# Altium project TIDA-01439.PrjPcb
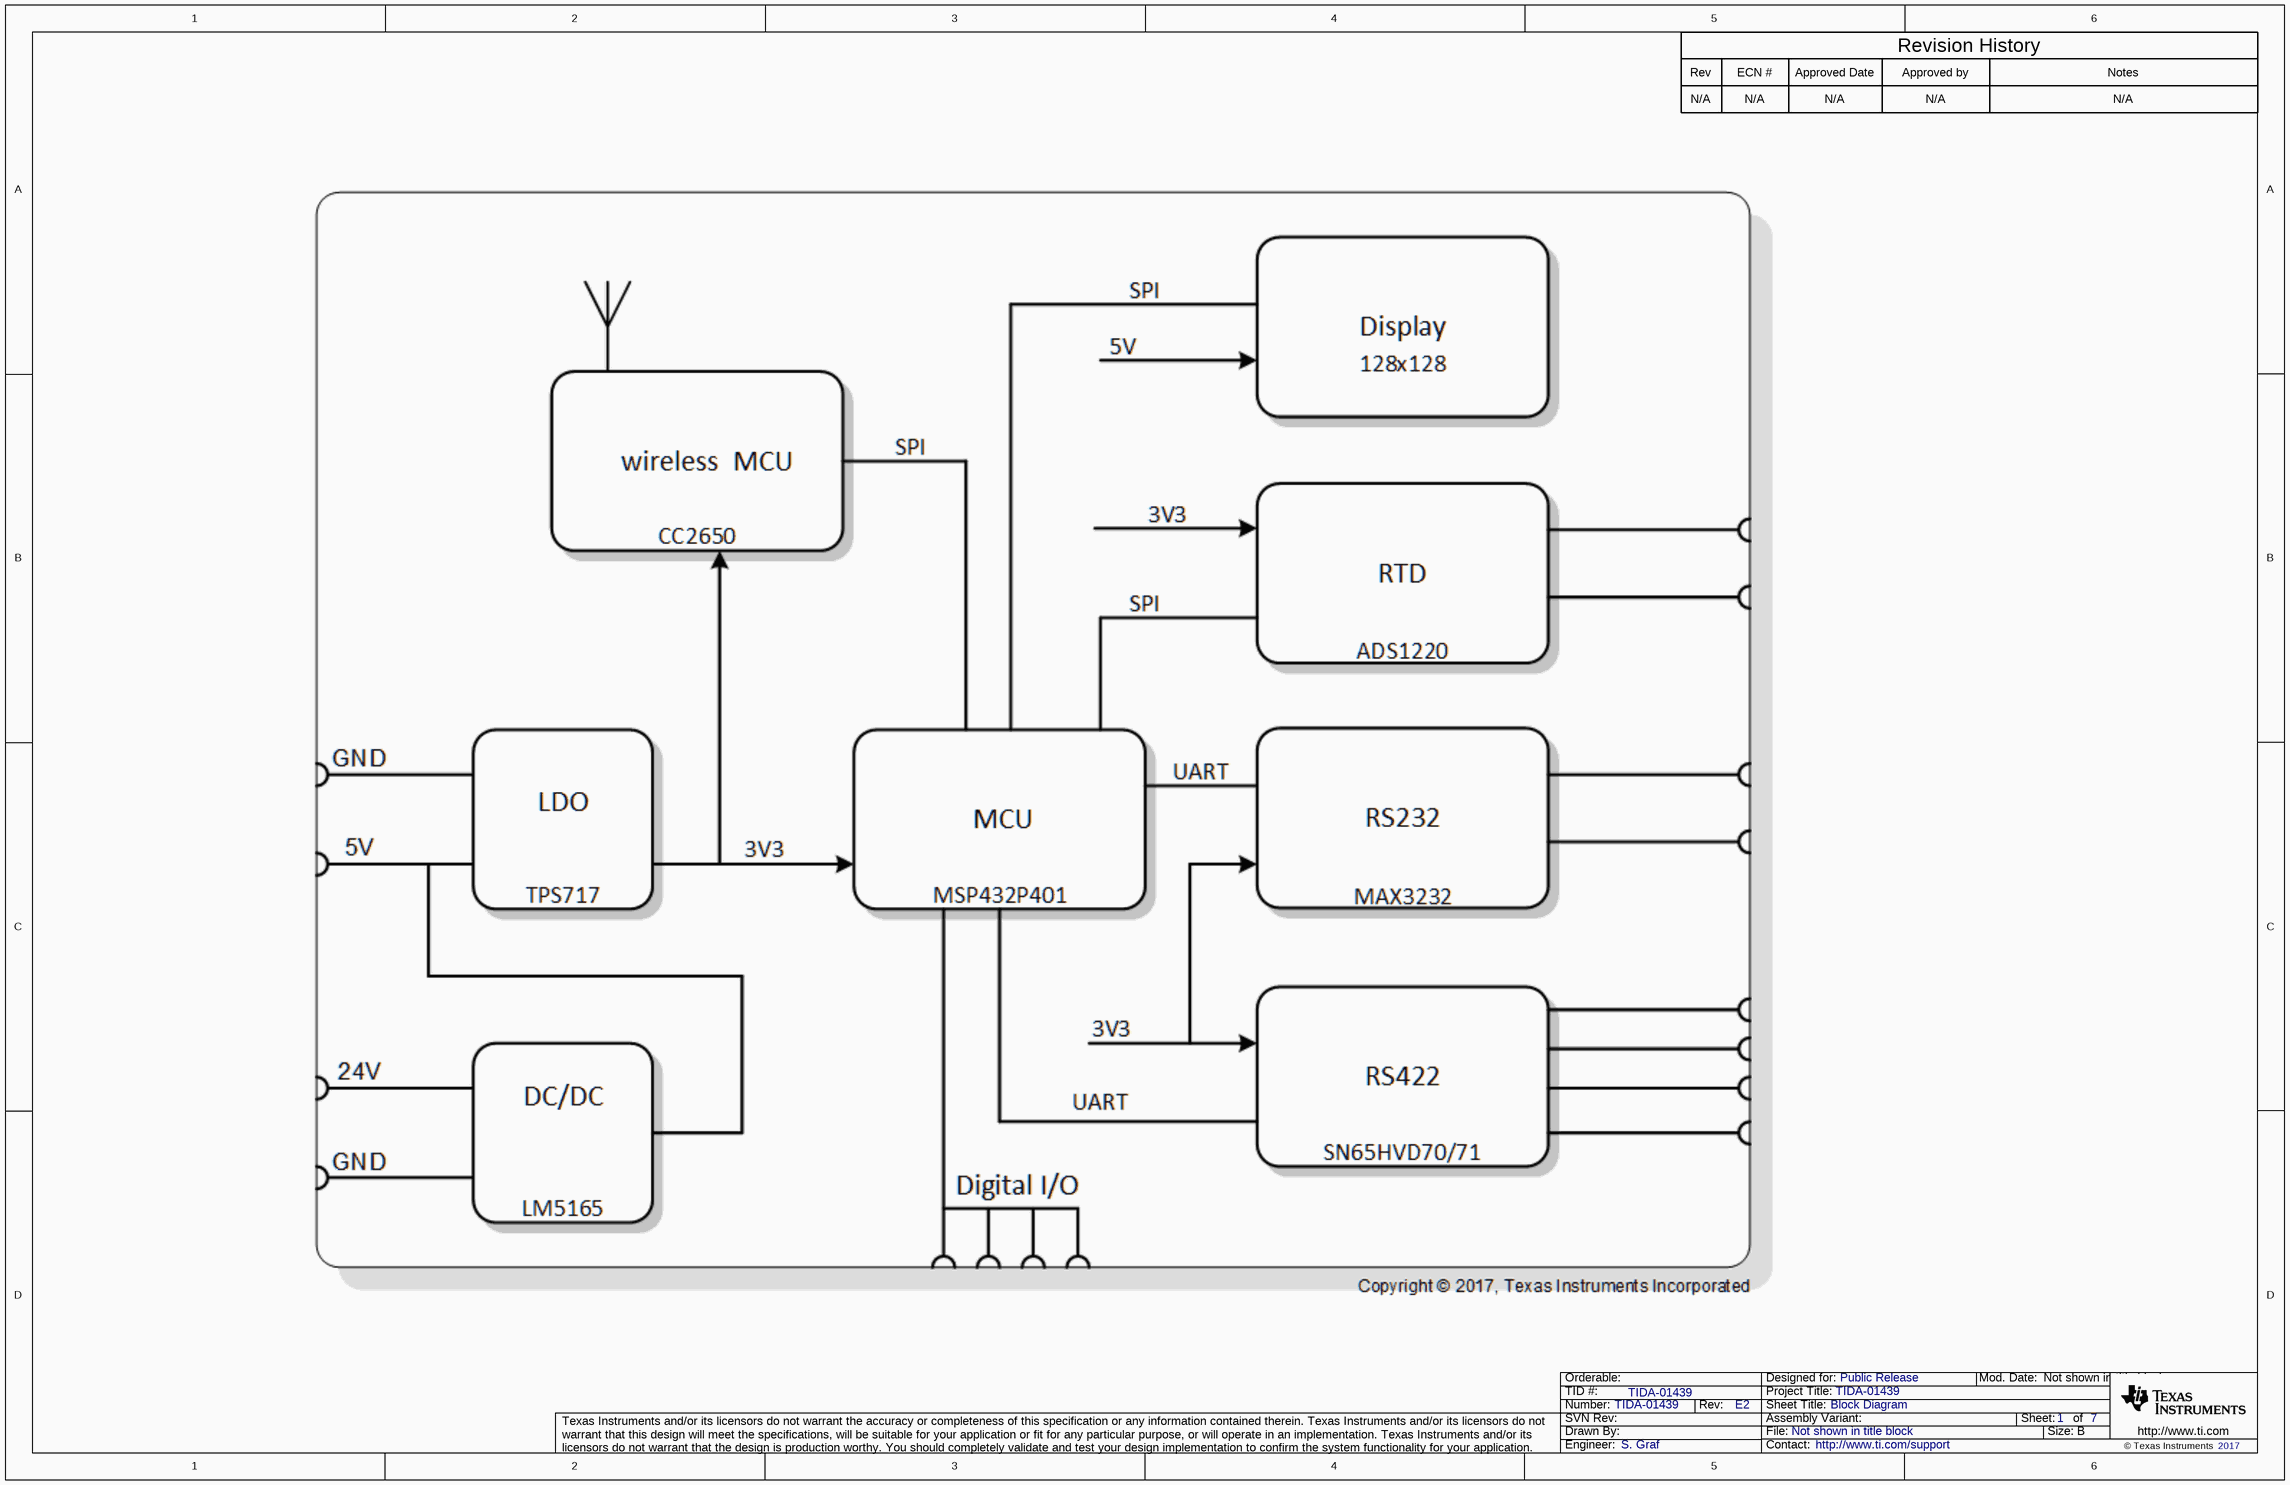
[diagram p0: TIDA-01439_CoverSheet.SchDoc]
CopyrightYear: 2017; PCB_Layout: K. Hacker (GCD); PCB_Rev: E2; PRJ_Customer: Public Release; PRJ_Engineer: S. Graf; PRJ_Number: TIDA-01439; PRJ_Title: TIDA-01439; SCH_Rev: E2; TechSupport: http://www.ti.com/support; TID: TIDA-01439
7 sheets, 144 parts. Net scope: global (net labels, ports and power ports of the same name join across sheets).
Board file: TIDA-01439_PCB.PcbDoc
Sheets:
  TIDA-01439_CoverSheet.SchDoc
  TIDA-01439_CC2650.SchDoc
  TIDA-01439_MSP432.SchDoc
  TIDA-01439_RTD.SchDoc
  TIDA-01439_Interface.SchDoc
  TIDA-01439_Powersupply.SchDoc
  TIDA-01439_EVM_Hardware.SchDoc

## Sheet TIDA-01439_CoverSheet.SchDoc: Block Diagram
size 431 x 279 mm; Date: Not shown in title block; ApprovedBy: Not shown in title block; CheckedBy: Not shown in title block; Author: Not shown in title block; CompanyName: Not shown in title block; Engineer: Not shown in title block; Organization: Not shown in title block; Address1: Not shown in title block; Address2: Not shown in title block; Address3: Not shown in title block; Address4: Not shown in title block; DocumentNumber: 1; Revision: Use project parameter SCH_Rev; SheetNumber: 1; SheetTotal: 7; PageSetup: Record=PageOptions¦CenterHorizontal=True¦CenterVertical=True¦PrintScale=1.00¦XCorrection=1.00¦YCorrection=1.00¦PrintKind=0¦BorderSize=5000000¦LeftOffset=0¦BottomOffset=0¦Orientation=2¦PaperLength=1000¦PaperWidth=1000¦Scale=100¦PaperSource=15¦PrintQuality=600¦MediaType=1¦DitherType=10¦PaperKind=Letter¦PrintScaleMode=1

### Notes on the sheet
- Rev
- N/A
- ECN #
- Approved Date
- Approved by
- Revision History
- Notes

## Sheet TIDA-01439_CC2650.SchDoc
size 431 x 279 mm; Date: Not shown in title block; ApprovedBy: Not shown in title block; CheckedBy: Not shown in title block; Author: Not shown in title block; CompanyName: Not shown in title block; Engineer: Not shown in title block; Organization: Not shown in title block; Address1: Not shown in title block; Address2: Not shown in title block; Address3: Not shown in title block; Address4: Not shown in title block; DocumentNumber: 1; Revision: Use project parameter SCH_Rev; SheetNumber: 2; SheetTotal: 7; PageSetup: Record=PageOptions¦CenterHorizontal=True¦CenterVertical=True¦PrintScale=1.00¦XCorrection=1.00¦YCorrection=1.00¦PrintKind=0¦BorderSize=5000000¦LeftOffset=0¦BottomOffset=0¦Orientation=2¦PaperLength=1000¦PaperWidth=1000¦Scale=100¦PaperSource=15¦PrintQuality=600¦MediaType=1¦DitherType=10¦PaperKind=Letter¦PrintScaleMode=1
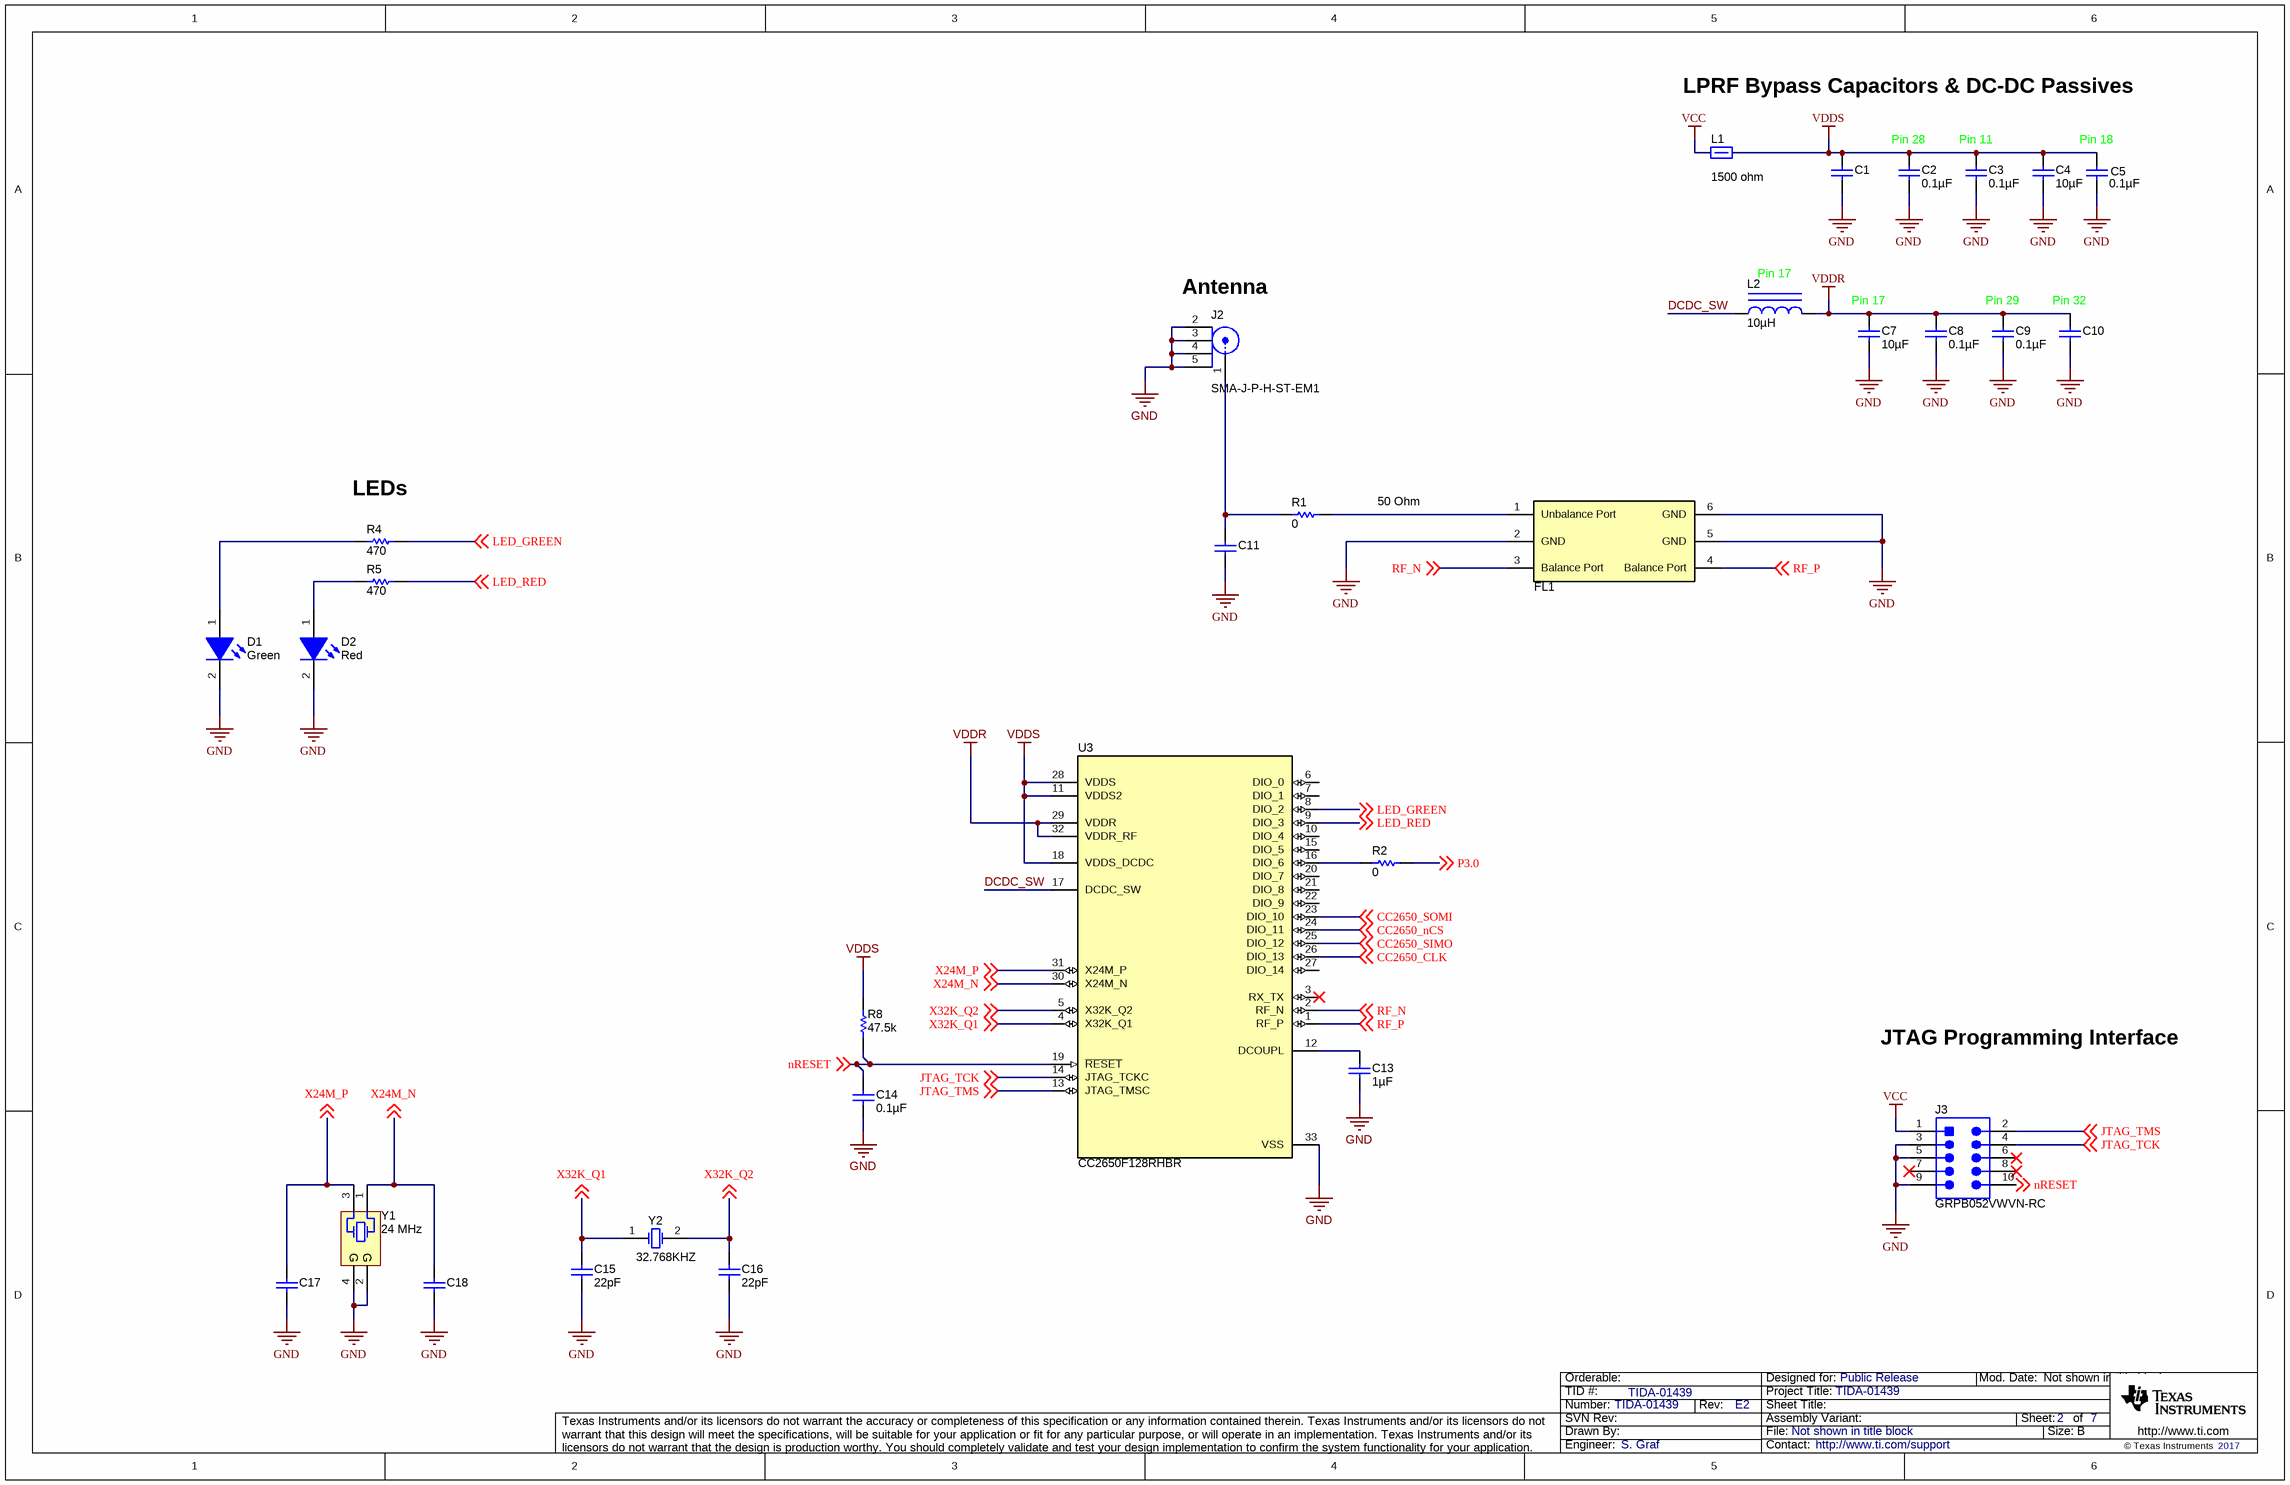
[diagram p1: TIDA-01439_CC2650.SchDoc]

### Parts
C1  Used in BOM report  [0603]  (value not drawn)
C2  ValueDisplayed: 0.1µF  [0402]  (hidden comment: GRM155R70J104KA01D)
C3  ValueDisplayed: 0.1µF  [0402]  (hidden comment: GRM155R70J104KA01D)
C4  ValueDisplayed: 10µF  [0805_HV]  (hidden comment: GRM21BR70J106KE76L)
C5  ValueDisplayed: 0.1µF  [0402]  (hidden comment: GRM155R70J104KA01D)
C7  ValueDisplayed: 10µF  [0805_HV]  (hidden comment: GRM21BR70J106KE76L)
C8  ValueDisplayed: 0.1µF  [0402]  (hidden comment: GRM155R70J104KA01D)
C9  ValueDisplayed: 0.1µF  [0402]  (hidden comment: GRM155R70J104KA01D)
C10  Used in BOM report  [0402]  (value not drawn)
C11  Used in BOM report  [0402]  (value not drawn)
C13  ValueDisplayed: 1µF  [0603]  (hidden comment: GRM188R70J105KA01D)
C14  ValueDisplayed: 0.1µF  [0402]  (hidden comment: GRM155R70J104KA01D)
C15  ValueDisplayed: 22pF  [0603]  (hidden comment: 06035A220JAT2A)
C16  ValueDisplayed: 22pF  [0603]  (hidden comment: 06035A220JAT2A)
C17  Used in BOM report  [0603]  (value not drawn)
C18  Used in BOM report  [0603]  (value not drawn)
D1  value Green  [KPTL-3216-01_Green]  (hidden comment: KPTL-3216CGCK-01)
D2  value Red  [KPTL-3216-01_Red]  (hidden comment: KPTL-3216SURCK-01)
FL1  LFB182G45BG5D920  [Murata_LFB182G45BG5D920]  (value not drawn)
J2  SMA-J-P-H-ST-EM1  [Samtec_SMA-J-P-H-ST-EM1]
J3  GRPB052VWVN-RC  [CONN_GRPB052VWVN-RC]
L1  value 1500 ohm  [0603]  (hidden comment: BLM18HE152SN1D)
L2  ValueDisplayed: 10µH  [0805_HV]  (hidden comment: CKS2125100M-T)
R1  ValueDisplayed: 0  [0402]  (hidden comment: CRCW04020000Z0ED)
R2  ValueDisplayed: 0  [0402]  (hidden comment: CRCW04020000Z0ED)
R4  ValueDisplayed: 470  [0402]  (hidden comment: CRCW0402470RJNED)
R5  ValueDisplayed: 470  [0402]  (hidden comment: CRCW0402470RJNED)
R8  ValueDisplayed: 47.5k  [0402]  (hidden comment: CRCW040247K5FKED)
U3  CC2650F128RHBR  [RHB0032E]
Y1  Frequency: 24 MHz  [EPSON_TSX-3225]  (hidden comment: TSX-3225 24.0000MF20G-AC3)
Y2  Frequency: 32.768KHZ  [Epson_FC-12M]  (hidden comment: FC-12M 32.7680KA-A3)

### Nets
GND: C1.2 C2.2 C3.2 C4.2 C5.2 C7.2 C8.2 C9.2 C10.2 C11.2 C13.2 C14.2 C15.1 C16.2 C17.2 C18.2 D1.2(K) D2.2(K) FL1.2(GND) FL1.5(GND) FL1.6(GND) J2.2 J2.3 J2.4 J2.5 J3.3 J3.5 J3.9 U3.33(VSS) Y1.2(GND) Y1.4(GND)
VCC: J3.1 L1.2
VDDR: C7.1 C8.1 C9.1 C10.1 L2.2 U3.29(VDDR) U3.32(VDDR_RF)
VDDS: C1.1 C2.1 C3.1 C4.1 C5.1 L1.1 R8.2 U3.11(VDDS2) U3.18(VDDS_DCDC) U3.28(VDDS)
CC2650_CLK: U3.26(DIO_13) ; off-sheet CC2650_CLK
CC2650_nCS: U3.24(DIO_11) ; off-sheet CC2650_nCS
CC2650_SIMO: U3.25(DIO_12) ; off-sheet CC2650_SIMO
CC2650_SOMI: U3.23(DIO_10) ; off-sheet CC2650_SOMI
DCDC_SW: L2.1 U3.17(DCDC_SW)
JTAG_TCK: J3.4 U3.14(JTAG_TCKC) ; off-sheet JTAG_TCK
JTAG_TMS: J3.2 U3.13(JTAG_TMSC) ; off-sheet JTAG_TMS
LED_GREEN: R4.2 U3.8(DIO_2) ; off-sheet LED_GREEN
LED_RED: R5.1 U3.9(DIO_3) ; off-sheet LED_RED
nRESET: C14.1 J3.10 R8.1 U3.19(~{RESET}) ; off-sheet nRESET
P3.0: R2.2 ; off-sheet P3.0
RF_N: FL1.3(Balance_Port) U3.2(RF_N) ; off-sheet RF_N
RF_P: FL1.4(Balance_Port) U3.1(RF_P) ; off-sheet RF_P
X24M_N: C18.1 U3.30(X24M_N) Y1.1 ; off-sheet X24M_N
X24M_P: C17.1 U3.31(X24M_P) Y1.3 ; off-sheet X24M_P
X32K_Q1: C15.2 U3.4(X32K_Q1) Y2.1(OSC1) ; off-sheet X32K_Q1
X32K_Q2: C16.1 U3.5(X32K_Q2) Y2.2(OSC2) ; off-sheet X32K_Q2
NetC11_1: C11.1 J2.1 R1.1
NetC13_1: C13.1 U3.12(DCOUPL)
NetD1_1: D1.1(A) R4.1
NetD2_1: D2.1(A) R5.2
NetFL1_1: FL1.1(Unbalance_Port) R1.2
NetR2_1: R2.1 U3.16(DIO_6)

Not connected (* = marked no-connect by the designer): J3 6* 7* 8*; U3 3(RX_TX)* 6(DIO_0) 7(DIO_1) 10(DIO_4) 15(DIO_5) 20(DIO_7) 21(DIO_8) 22(DIO_9) 27(DIO_14)

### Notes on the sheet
- LPRF Bypass Capacitors & DC-DC Passives
- (near C2) Pin 28
- (near C3) Pin 11
- (near C5) Pin 18
- (near J2) Antenna
- (near L2) Pin 17
- (near C7) Pin 17
- (near C9) Pin 29
- (near C10) Pin 32
- (near R4) LEDs
- 50 Ohm
- JTAG Programming Interface

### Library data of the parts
C1 C10 C11 C17 C18 = Capacitor: CAP, CERM, xxxF, xxV, [TempCo], xx%, [PackageReference]; Polarized: N; U/M: EA
C2 C3 C5 C8 C9 C14 = GRM155R70J104KA01D: CAP, CERM, 0.1 µF, 6.3 V, +/- 10%, X7R, 0402; Manufacturer: MuRata; Polarized: N; CompType: Capacitor; Value: 0.1uF; U/M: EA; Cap_F: 0.0000001; Tolerance_%: 10; Value1: Unknown; VDC_V: 6.3; Value2: 6.3V; TaMin_C: -55; TaMax_C: 125; AEC Category: Q200
C4 C7 = GRM21BR70J106KE76L: CAP, CERM, 10 µF, 6.3 V, +/- 10%, X7R, 0805; Manufacturer: MuRata; Polarized: N; CompType: Capacitor; Value: 10uF; U/M: EA; Cap_F: 0.00001; Tolerance_%: 10; Value1: Unknown; VDC_V: 6.3; Value2: 6.3V; TaMin_C: -55; TaMax_C: 125; Cap_Case: 0805; AEC Category: Q200
C13 = GRM188R70J105KA01D: CAP, CERM, 1 µF, 6.3 V, +/- 10%, X7R, 0603; Manufacturer: MuRata; Polarized: N; CompType: Capacitor; Value: 1uF; U/M: EA; Cap_F: 0.000001; Tolerance_%: 10; Value1: Unknown; VDC_V: 6.3; Value2: 6.3V; TaMin_C: -55; TaMax_C: 125; AEC Category: Q200
C15 C16 = 06035A220JAT2A: CAP, CERM, 22 pF, 50 V,+/- 5%, C0G/NP0, 0603; Manufacturer: AVX; Polarized: N; CompType: Capacitor; Value: 22pF; U/M: EA; Cap_F: 0.000000000022; Tolerance_%: 5; ESR_ohm: 0.259; Value1: 0.259 ohm; VDC_V: 50; Value2: 50V; TaMin_C: -55; TaMax_C: 125; SizeArea_mm2: 1.28; SizeAreaWB_mm2: 4.68; SizeX_mm: 1.6; SizeY_mm: 0.8; SizeZ_mm: 1; AEC Category: Q200; Green_Lifecycle: Active; Green_REACh: Passed
D1 = KPTL-3216CGCK-01: LED, Green, SMD; Manufacturer: Kingbright; Type: AlInGaP; Vf_V: 2.1; Value2: 2.1V; Io_A: 0.02; Vr_V: 5; Ir_A: 1e-005; Tjmax_C: 85; Power_TotalModule: 0.075; Value1: 0.075W; Angle: 70; U/M: EA; SizeAreaWB_mm2: 10.92; SizeArea_mm2: 5.12; SizeX_mm: 3.2; SizeY_mm: 1.6; SizeZ_mm: 0.35
D2 = KPTL-3216SURCK-01: LED, Red, SMD; Manufacturer: Kingbright; Type: AlInGaP; Vf_V: 1.95; Value2: 1.95V; Io_A: 0.02; Vr_V: 5; Ir_A: 1e-005; Tjmax_C: 85; Power_TotalModule: 0.075; Value1: 0.075W; Angle: 70; U/M: EA; SizeAreaWB_mm2: 10.92; SizeArea_mm2: 5.12; SizeX_mm: 3.2; SizeY_mm: 1.6; SizeZ_mm: 0.35
FL1 = LFB182G45BG5D920: Filter, BandPass, 2.45GHz, SMD; Manufacturer: MuRata; SymbolCreator: Altium
J2 = SMA-J-P-H-ST-EM1: SMA Jack, 50 Ohm, Gold, R/A, SMT; Manufacturer: Samtec; SymbolCreator: X0208326; Pitch_mm: 2.825; Gender: Female; Shrouded: Y; Voltage_V: 335
J3 = GRPB052VWVN-RC: Header, 50mil, 5x2, Gold, TH; Manufacturer: Sullins Connector Solutions; SymbolCreator: a0412235; U/M: EA
L1 = BLM18HE152SN1D: Ferrite Bead, 1500 ohm @ 100 MHz, 0.5 A, 0603; Manufacturer: MuRata; Imax_A: 0.5; Value1: 0.5 ohm; Value2: 0.5A; ZTyp@100MHz_Ohm: 1500
L2 = CKS2125100M-T: Inductor, Multilayer, Ferrite, 10 µH, 0.11 A, 0.52 ohm, SMD; Manufacturer: Taiyo Yuden; Value: 10uH; Ind_H: 10.0E-6; Imax_A: 0.11; DCR_ohm: 0.52; Value2: 0.11A; SizeAreaWB_mm2: 6.75; SizeArea_mm2: 2.5; SizeX_mm: 2; SizeY_mm: 1.25; SizeZ_mm: 1.45; AEC Category: Q200
R1 R2 = CRCW04020000Z0ED: RES, 0, 5%, 0.063 W, 0402; Manufacturer: Vishay-Dale; CompType: Resistor; Value: 0; Value_Code: 0000; Tolerance_%: 5; Power_W: 0.063; Value2: 0.063W; VDC_V: 50; TempCo: 200 ppm/C; SizeArea_mm2: 0.5; SizeX_mm: 1; SizeZ_mm: 0.6; EIA_Code: E24; U/M: EA; AEC Category: Q200; Green_Lifecycle: Active; Green_REACh: Passed
R4 R5 = CRCW0402470RJNED: RES, 470, 5%, 0.063 W, 0402; Manufacturer: Vishay-Dale; CompType: Resistor; Value: 470; Value_Code: 470R; Tolerance_%: 5; Power_W: 0.063; Value2: 0.063W; VDC_V: 50; TempCo: 200 ppm/C; EIA_Code: E24; U/M: EA; AEC Category: Q200
R8 = CRCW040247K5FKED: RES, 47.5 k, 1%, 0.063 W, 0402; Manufacturer: Vishay-Dale; CompType: Resistor; Value: 47.5k; Res_ohm: 47500; Value_Code: 47k5; Tolerance_%: 1; Power_W: 0.063; Value2: 0.063W; VDC_V: 50; TempCo: 100 ppm/C; EIA_Code: E96; U/M: EA; AEC Category: Q200
U3 = CC2650F128RHBR: Ultra low-power ARM Cortex M3 2.4 GHz Radio MCU, Multi-Protocol, RSHB032E; Alternate PartNumber: CC2650F128RHBT; Manufacturer: Texas Instruments; SymbolCreator: a0412235; CompType: IC; U/M: EA
Y1 = TSX-3225 24.0000MF20G-AC3: Crystal, 24 MHz, 9 pF, SMD; Manufacturer: Epson; SymbolCreator: a0412235; U/M: EA; TaMin_C: -40; TaMax_C: 85; Frequency Stability: ±20ppm
Y2 = FC-12M 32.7680KA-A3: Crystal, 32.768kHz, 12.5pF, SMD; Manufacturer: Epson; SymbolCreator: a0412235; U/M: EA; TaMin_C: -40; TaMax_C: 85; Frequency Stability: ±20ppm

## Sheet TIDA-01439_MSP432.SchDoc
size 431 x 279 mm; Date: Not shown in title block; ApprovedBy: Not shown in title block; CheckedBy: Not shown in title block; Author: Not shown in title block; CompanyName: Not shown in title block; Engineer: Not shown in title block; Organization: Not shown in title block; Address1: Not shown in title block; Address2: Not shown in title block; Address3: Not shown in title block; Address4: Not shown in title block; DocumentNumber: 1; Revision: Use project parameter SCH_Rev; SheetNumber: 3; SheetTotal: 7; PageSetup: Record=PageOptions¦CenterHorizontal=True¦CenterVertical=True¦PrintScale=1.00¦XCorrection=1.00¦YCorrection=1.00¦PrintKind=0¦BorderSize=5000000¦LeftOffset=0¦BottomOffset=0¦Orientation=2¦PaperLength=1000¦PaperWidth=1000¦Scale=100¦PaperSource=15¦PrintQuality=600¦MediaType=1¦DitherType=10¦PaperKind=Letter¦PrintScaleMode=1
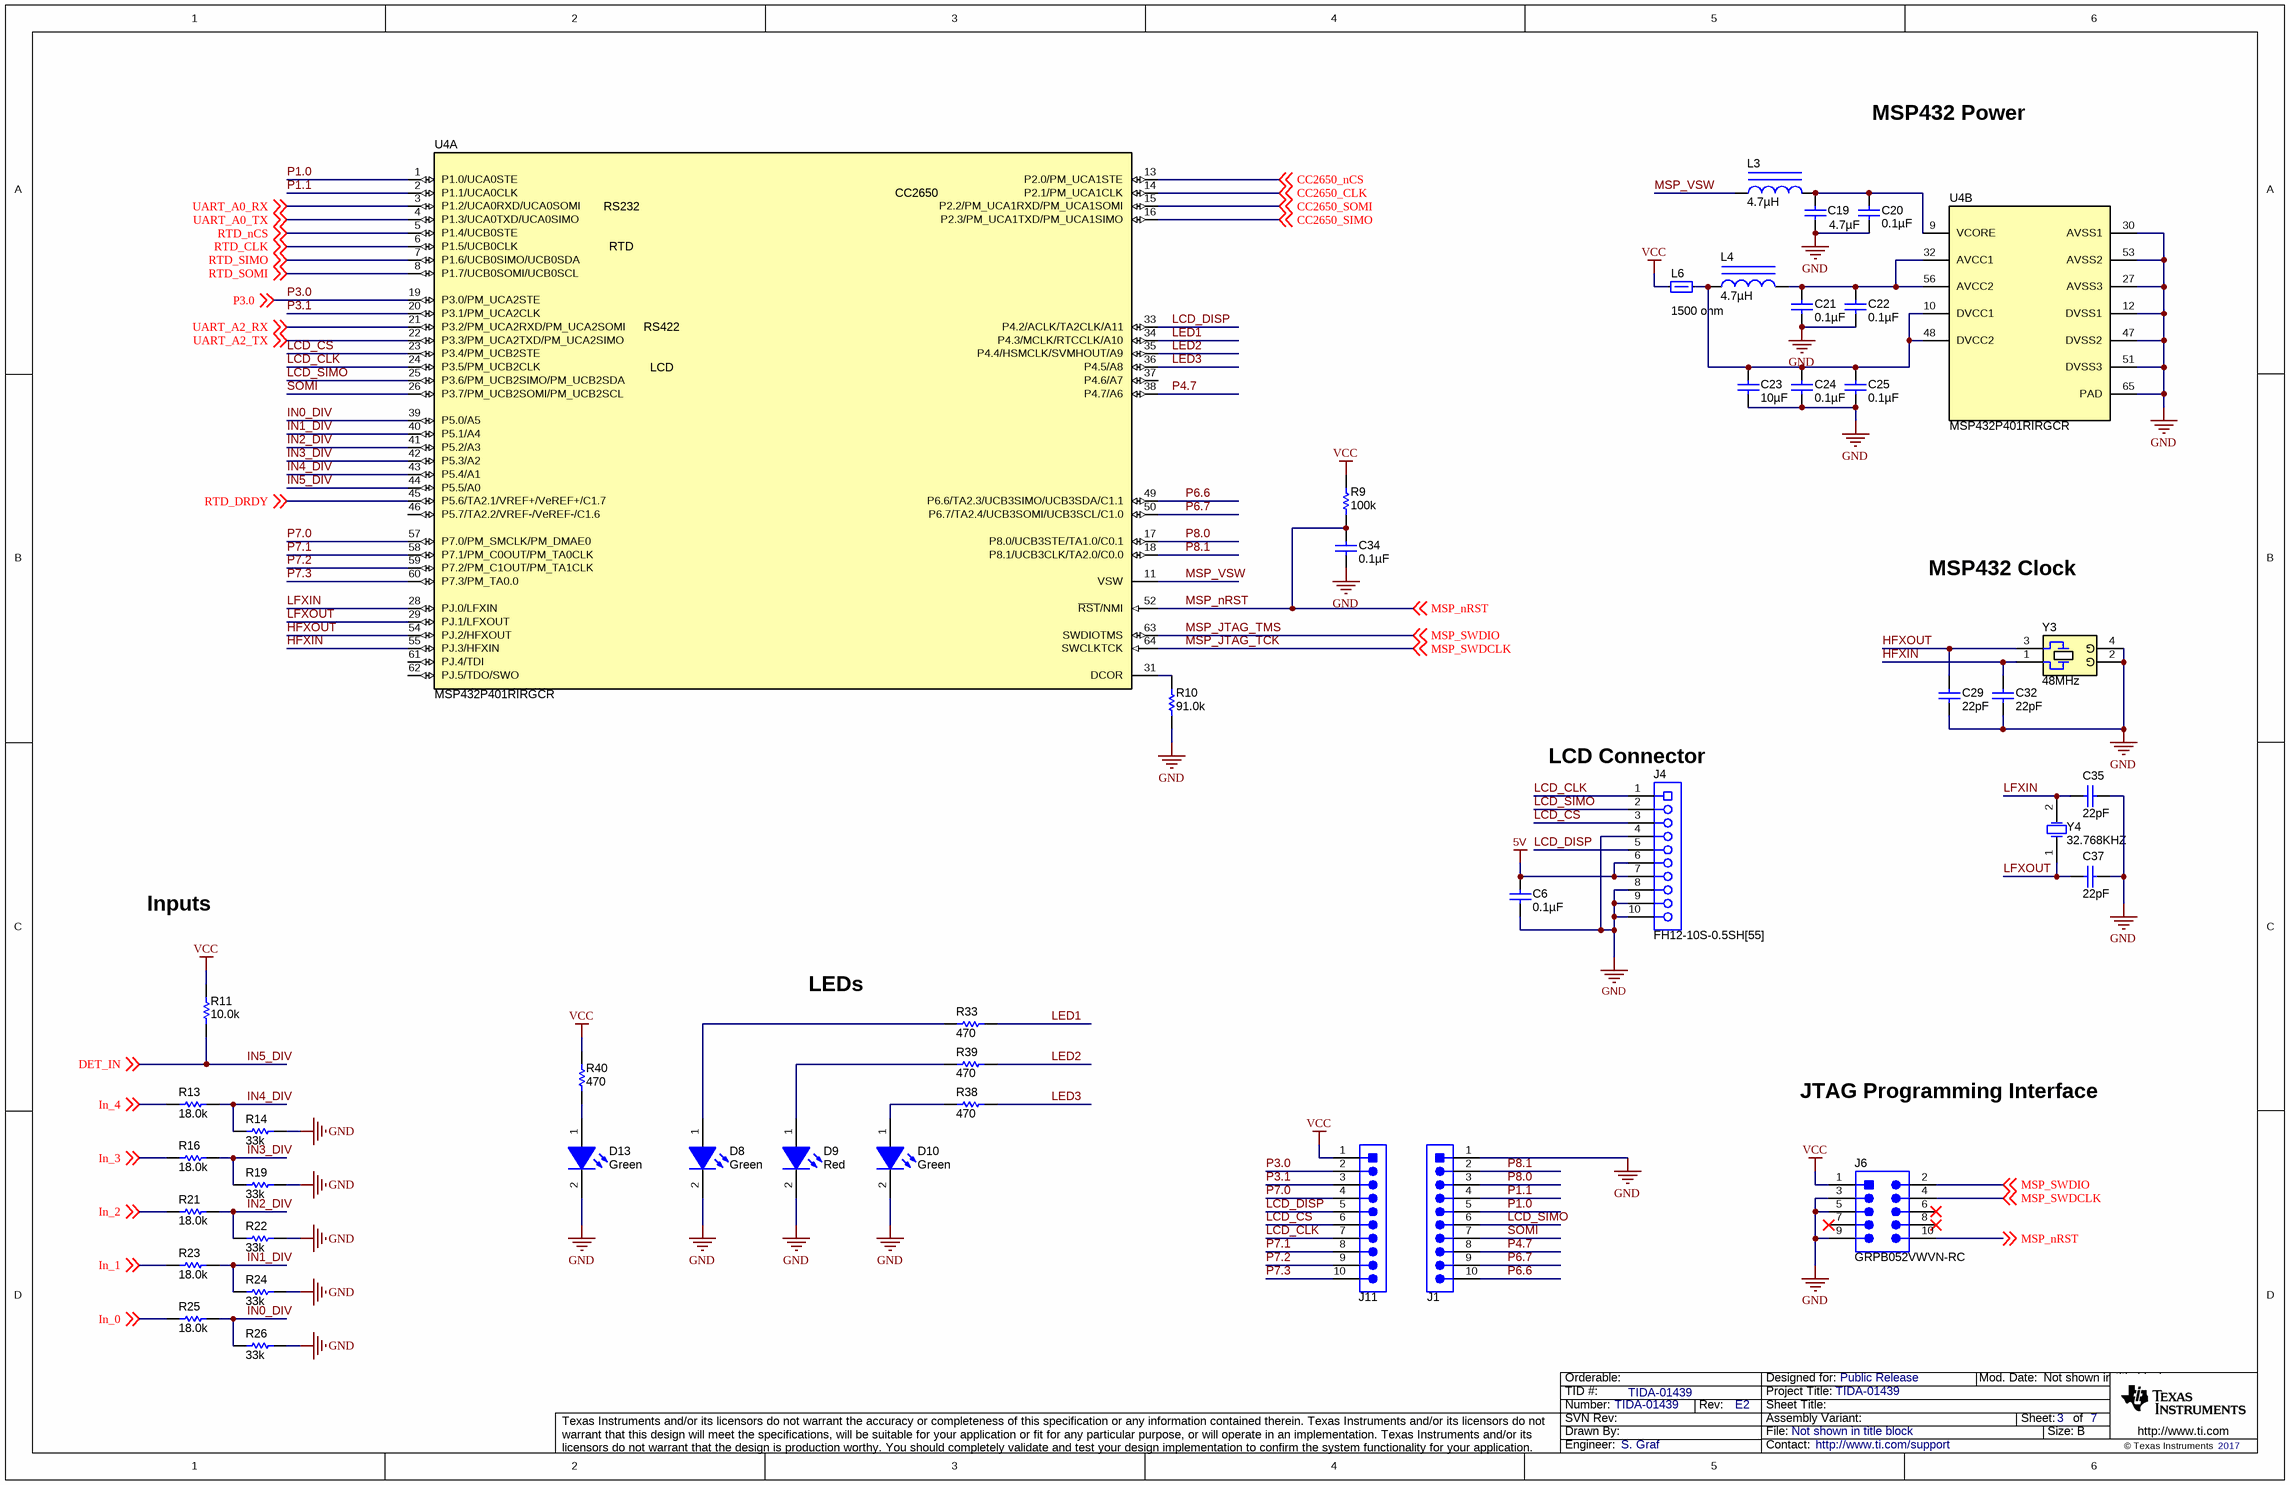
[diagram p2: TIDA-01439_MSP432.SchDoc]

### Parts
C6  ValueDisplayed: 0.1µF  [0402]  (hidden comment: GRM155R70J104KA01D)
C19  ValueDisplayed: 4.7µF  [0805_HV]  (hidden comment: CC0805ZRY5V6BB475)
C20  ValueDisplayed: 0.1µF  [0402]  (hidden comment: GRM155R70J104KA01D)
C21  ValueDisplayed: 0.1µF  [0402]  (hidden comment: GRM155R70J104KA01D)
C22  ValueDisplayed: 0.1µF  [0402]  (hidden comment: GRM155R70J104KA01D)
C23  ValueDisplayed: 10µF  [0603]  (hidden comment: GRM188R60J106ME47D)
C24  ValueDisplayed: 0.1µF  [0402]  (hidden comment: GRM155R70J104KA01D)
C25  ValueDisplayed: 0.1µF  [0402]  (hidden comment: GRM155R70J104KA01D)
C29  ValueDisplayed: 22pF  [0402]  (hidden comment: GRM1555C1H220JA01D)
C32  ValueDisplayed: 22pF  [0402]  (hidden comment: GRM1555C1H220JA01D)
C34  ValueDisplayed: 0.1µF  [0402]  (hidden comment: GRM155R70J104KA01D)
C35  ValueDisplayed: 22pF  [0402]  (hidden comment: GRM1555C1H220JA01D)
C37  ValueDisplayed: 22pF  [0402]  (hidden comment: GRM1555C1H220JA01D)
D8  value Green  [KPTL-3216-01_Green]  (hidden comment: KPTL-3216CGCK-01)
D9  value Red  [KPTL-3216-01_Red]  (hidden comment: KPTL-3216SURCK-01)
D10  value Green  [KPTL-3216-01_Green]  (hidden comment: KPTL-3216CGCK-01)
D13  value Green  [KPTL-3216-01_Green]  (hidden comment: KPTL-3216CGCK-01)
J1  61301011121  [Wurth_61301011121]  (value not drawn)
J4  FH12-10S-0.5SH[55]  [Hirose_FH12-10S-0_5SH[55]]
J6  GRPB052VWVN-RC  [CONN_GRPB052VWVN-RC]
J11  61301011121  [Wurth_61301011121]  (value not drawn)
L3  ValueDisplayed: 4.7µH  [MLP2520S-S]  (hidden comment: MLP2520S4R7ST0S1)
L4  ValueDisplayed: 4.7µH  [MLP2520S-S]  (hidden comment: MLP2520S4R7ST0S1)
L6  value 1500 ohm  [0603]  (hidden comment: BLM18HE152SN1D)
R9  ValueDisplayed: 100k  [0402]  (hidden comment: CRCW0402100KJNED)
R10  ValueDisplayed: 91.0k  [0603]  (hidden comment: RG1608P-913-B-T5)
R11  ValueDisplayed: 10.0k  [0402]  (hidden comment: CRCW040210K0FKED)
R13  ValueDisplayed: 18.0k  [0402]  (hidden comment: CRCW040218K0FKED)
R14  ValueDisplayed: 33k  [0402]  (hidden comment: CRCW040233K0JNED)
R16  ValueDisplayed: 18.0k  [0402]  (hidden comment: CRCW040218K0FKED)
R19  ValueDisplayed: 33k  [0402]  (hidden comment: CRCW040233K0JNED)
R21  ValueDisplayed: 18.0k  [0402]  (hidden comment: CRCW040218K0FKED)
R22  ValueDisplayed: 33k  [0402]  (hidden comment: CRCW040233K0JNED)
R23  ValueDisplayed: 18.0k  [0402]  (hidden comment: CRCW040218K0FKED)
R24  ValueDisplayed: 33k  [0402]  (hidden comment: CRCW040233K0JNED)
R25  ValueDisplayed: 18.0k  [0402]  (hidden comment: CRCW040218K0FKED)
R26  ValueDisplayed: 33k  [0402]  (hidden comment: CRCW040233K0JNED)
R33  ValueDisplayed: 470  [0402]  (hidden comment: CRCW0402470RJNED)
R38  ValueDisplayed: 470  [0402]  (hidden comment: CRCW0402470RJNED)
R39  ValueDisplayed: 470  [0402]  (hidden comment: CRCW0402470RJNED)
R40  ValueDisplayed: 470  [0402]  (hidden comment: CRCW0402470RJNED)
U4  MSP432P401RIRGCR  [RGC0064B]  (parts A,B of 2)
Y3  Frequency: 48MHz  [Epson_FA-238]  (hidden comment: FA-238 48.0000MB-W0)
Y4  Frequency: 32.768KHZ  [Epson_FC-12M]  (hidden comment: FC-12M 32.7680KA-A3)

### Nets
5V: C6.1 J4.6 J4.7
GND: C6.2 C19.2 C20.2 C21.2 C22.2 C23.2 C24.2 C25.2 C29.1 C32.2 C34.2 C35.1 C37.1 D8.2(K) D9.2(K) D10.2(K) D13.2(K) J1.1 J4.4 J4.8 J4.9 J4.10 J6.3 J6.5 J6.9 R10.1 R14.1 R19.1 R22.1 R24.1 R26.1 U4.12(DVSS1) U4.27(AVSS3) U4.30(AVSS1) U4.47(DVSS2) U4.51(DVSS3) U4.53(AVSS2) U4.65(PAD) Y3.2(GND) Y3.4(GND)
VCC: J6.1 J11.1 L6.2 R9.2 R11.2 R40.1
CC2650_CLK: U4.14(P2.1/PM_UCA1CLK) ; off-sheet CC2650_CLK
CC2650_nCS: U4.13(P2.0/PM_UCA1STE) ; off-sheet CC2650_nCS
CC2650_SIMO: U4.16(P2.3/PM_UCA1TXD/PM_UCA1SIMO) ; off-sheet CC2650_SIMO
CC2650_SOMI: U4.15(P2.2/PM_UCA1RXD/PM_UCA1SOMI) ; off-sheet CC2650_SOMI
HFXIN: C32.1 U4.55(PJ.3/HFXIN) Y3.1
HFXOUT: C29.2 U4.54(PJ.2/HFXOUT) Y3.3
IN0_DIV: R25.1 R26.2 U4.39(P5.0/A5)
IN1_DIV: R23.1 R24.2 U4.40(P5.1/A4)
IN2_DIV: R21.1 R22.2 U4.41(P5.2/A3)
IN3_DIV: R16.1 R19.2 U4.42(P5.3/A2)
IN4_DIV: R13.1 R14.2 U4.43(P5.4/A1)
IN5_DIV: R11.1 U4.44(P5.5/A0) ; off-sheet DET_IN  [also labelled DET_IN]
In_0: R25.2 ; off-sheet In_0
In_1: R23.2 ; off-sheet In_1
In_2: R21.2 ; off-sheet In_2
In_3: R16.2 ; off-sheet In_3
In_4: R13.2 ; off-sheet In_4
LCD_CLK: J4.1 J11.7 U4.24(P3.5/PM_UCB2CLK)
LCD_CS: J4.3 J11.6 U4.23(P3.4/PM_UCB2STE)
LCD_DISP: J4.5 J11.5 U4.33(P4.2/ACLK/TA2CLK/A11)
LCD_SIMO: J1.6 J4.2 U4.25(P3.6/PM_UCB2SIMO/PM_UCB2SDA)
LED1: R33.2 U4.34(P4.3/MCLK/RTCCLK/A10)
LED2: R39.1 U4.35(P4.4/HSMCLK/SVMHOUT/A9)
LED3: R38.1 U4.36(P4.5/A8)
LFXIN: C35.2 U4.28(PJ.0/LFXIN) Y4.2(OSC2)
LFXOUT: C37.2 U4.29(PJ.1/LFXOUT) Y4.1(OSC1)
MSP_JTAG_TCK: J6.4 U4.64(SWCLKTCK) ; off-sheet MSP_SWDCLK  [also labelled MSP_SWDCLK]
MSP_JTAG_TMS: J6.2 U4.63(SWDIOTMS) ; off-sheet MSP_SWDIO  [also labelled MSP_SWDIO]
MSP_nRST: C34.1 J6.10 R9.1 U4.52(~{RST}/NMI) ; off-sheet MSP_nRST
MSP_VSW: L3.1 U4.11(VSW)
P1.0: J1.5 U4.1(P1.0/UCA0STE)
P1.1: J1.4 U4.2(P1.1/UCA0CLK)
P3.0: J11.2 U4.19(P3.0/PM_UCA2STE) ; off-sheet P3.0
P3.1: J11.3 U4.20(P3.1/PM_UCA2CLK)
P4.7: J1.8 U4.38(P4.7/A6)
P6.6: J1.10 U4.49(P6.6/TA2.3/UCB3SIMO/UCB3SDA/C1.1)
P6.7: J1.9 U4.50(P6.7/TA2.4/UCB3SOMI/UCB3SCL/C1.0)
P7.0: J11.4 U4.57(P7.0/PM_SMCLK/PM_DMAE0)
P7.1: J11.8 U4.58(P7.1/PM_C0OUT/PM_TA0CLK)
P7.2: J11.9 U4.59(P7.2/PM_C1OUT/PM_TA1CLK)
P7.3: J11.10 U4.60(P7.3/PM_TA0.0)
P8.0: J1.3 U4.17(P8.0/UCB3STE/TA1.0/C0.1)
P8.1: J1.2 U4.18(P8.1/UCB3CLK/TA2.0/C0.0)
RTD_CLK: U4.6(P1.5/UCB0CLK) ; off-sheet RTD_CLK
RTD_DRDY: U4.45(P5.6/TA2.1/VREF+/VeREF+/C1.7) ; off-sheet RTD_DRDY
RTD_nCS: U4.5(P1.4/UCB0STE) ; off-sheet RTD_nCS
RTD_SIMO: U4.7(P1.6/UCB0SIMO/UCB0SDA) ; off-sheet RTD_SIMO
RTD_SOMI: U4.8(P1.7/UCB0SOMI/UCB0SCL) ; off-sheet RTD_SOMI
SOMI: J1.7 U4.26(P3.7/PM_UCB2SOMI/PM_UCB2SCL)
UART_A0_RX: U4.3(P1.2/UCA0RXD/UCA0SOMI) ; off-sheet UART_A0_RX
UART_A0_TX: U4.4(P1.3/UCA0TXD/UCA0SIMO) ; off-sheet UART_A0_TX
UART_A2_RX: U4.21(P3.2/PM_UCA2RXD/PM_UCA2SOMI) ; off-sheet UART_A2_RX
UART_A2_TX: U4.22(P3.3/PM_UCA2TXD/PM_UCA2SIMO) ; off-sheet UART_A2_TX
NetC19_1: C19.1 C20.1 L3.2 U4.9(VCORE)
NetC21_1: C21.1 C22.1 L4.2 U4.32(AVCC1) U4.56(AVCC2)
NetC23_1: C23.1 C24.1 C25.1 L4.1 L6.1 U4.10(DVCC1) U4.48(DVCC2)
NetD8_1: D8.1(A) R33.1
NetD9_1: D9.1(A) R39.2
NetD10_1: D10.1(A) R38.2
NetD13_1: D13.1(A) R40.2
NetR10_2: R10.2 U4.31(DCOR)

Not connected (* = marked no-connect by the designer): J6 6* 7* 8*; U4 37(P4.6/A7) 46(P5.7/TA2.2/VREF-/VeREF-/C1.6) 61(PJ.4/TDI) 62(PJ.5/TDO/SWO)

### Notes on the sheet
- MSP432 Power
- (near U4) RS232
- (near U4) CC2650
- (near U4) RTD
- (near U4) RS422
- (near U4) LCD
- MSP432 Clock
- (near J4) LCD Connector
- Inputs
- LEDs
- JTAG Programming Interface

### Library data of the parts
C6 C20-C22 C24 C25 C34 = GRM155R70J104KA01D: CAP, CERM, 0.1 µF, 6.3 V, +/- 10%, X7R, 0402; Manufacturer: MuRata; Polarized: N; CompType: Capacitor; Value: 0.1uF; U/M: EA; Cap_F: 0.0000001; Tolerance_%: 10; Value1: Unknown; VDC_V: 6.3; Value2: 6.3V; TaMin_C: -55; TaMax_C: 125; SizeArea_mm2: 0.5; SizeAreaWB_mm2: 3; SizeX_mm: 1; SizeZ_mm: 0.6; AEC Category: Q200
C19 = CC0805ZRY5V6BB475: CAP, CERM, 4.7 µF, 10 V, +80/-20%, Y5V, 0805; Manufacturer: Yageo America; Polarized: N; CompType: Capacitor; Value: 4.7uF; U/M: EA; Cap_F: 0.0000047; Tolerance_%: 80; Value1: Unknown; VDC_V: 10; Value2: 10V; TaMin_C: -30; TaMax_C: 85; Cap_Case: 0805; SizeArea_mm2: 2.5; SizeAreaWB_mm2: 6.75; SizeX_mm: 2; SizeY_mm: 1.25; SizeZ_mm: 1.45; AEC Category: Q200
C23 = GRM188R60J106ME47D: CAP, CERM, 10 µF, 6.3 V, +/- 20%, X5R, 0603; Manufacturer: MuRata; Polarized: N; CompType: Capacitor; Value: 10uF; U/M: EA; Cap_F: 0.00001; Tolerance_%: 20; ESR_ohm: 0.009; Value1: 0.009 ohm; VDC_V: 6.3; Value2: 6.3V; IRMS_A: 2.74; TaMin_C: -55; TaMax_C: 125; SizeArea_mm2: 1.28; SizeAreaWB_mm2: 4.68; SizeX_mm: 1.6; SizeY_mm: 0.8; SizeZ_mm: 1; AEC Category: Q200
C29 C32 C35 C37 = GRM1555C1H220JA01D: CAP, CERM, 22 pF, 50 V, +/- 5%, C0G/NP0, 0402; Manufacturer: MuRata; Polarized: N; CompType: Capacitor; Value: 22pF; U/M: EA; Cap_F: 0.000000000022; Tolerance_%: 5; Value1: Unknown; VDC_V: 50; Value2: 50V; TaMin_C: -55; TaMax_C: 125; SizeArea_mm2: 0.5; SizeAreaWB_mm2: 3; SizeX_mm: 1; SizeZ_mm: 0.6; AEC Category: Q200
D8 D10 D13 = KPTL-3216CGCK-01: as D1 on sheet TIDA-01439_CC2650
D9 = KPTL-3216SURCK-01: as D2 on sheet TIDA-01439_CC2650
J1 J11 = 61301011121: Header, 2.54mm, 10x1, Gold, TH; Manufacturer: Wurth Elektronik; SymbolCreator: a0412235; Pitch_mm: 2.54; Gender: Male; Shrouded: N; Row_Count: 1
J4 = FH12-10S-0.5SH[55]: Connector, FPC 10 Pos. 9.1x2.0x5.6 mm; Manufacturer: Hirose Electric Co. Ltd.; SymbolCreator: a0411947
J6 = GRPB052VWVN-RC: as J3 on sheet TIDA-01439_CC2650
L3 L4 = MLP2520S4R7ST0S1: Inductor, Multilayer, Ferrite, 4.7 µH, 0.3 A, 0.143 ohm, SMD; Manufacturer: TDK; Value: 4.7uH; Ind_H: 4.7E-6; Imax_A: 0.3; Irms: 1.4A @ 40C rise; Isat: 0.3A @ 30% inductance drop; DCR_ohm: 0.143; Value2: 0.3A; SizeAreaWB_mm2: 11.84; SizeArea_mm2: 5.94; SizeX_mm: 2.7; SizeY_mm: 2.2; SizeZ_mm: 1.2; AEC Category: Q200
L6 = BLM18HE152SN1D: as L1 on sheet TIDA-01439_CC2650
R9 = CRCW0402100KJNED: RES, 100 k, 5%, 0.063 W, 0402; Manufacturer: Vishay-Dale; CompType: Resistor; Value: 100k; Res_ohm: 100000; Tolerance_%: 5; Power_W: 0.063; Value2: 0.063W; VDC_V: 50; TempCo: 200 ppm/C; SizeArea_mm2: 0.5; SizeX_mm: 1; SizeZ_mm: 0.6; EIA_Code: E24; U/M: EA; AEC Category: Q200
R10 = RG1608P-913-B-T5: RES, 91.0 k, 0.1%, 0.1 W, 0603; Manufacturer: Susumu Co Ltd; CompType: Resistor; Value: 91.0k; Res_ohm: 91000; Value_Code: 91k0; Tolerance_%: 0.1; Value2: 0.1W; VDC_V: 75; TempCo: 25 ppm/C; SizeArea_mm2: 1.28; SizeX_mm: 1.6; SizeY_mm: 0.8; SizeZ_mm: 1; U/M: EA; AEC Category: Q200
R11 = CRCW040210K0FKED: RES, 10.0 k, 1%, 0.063 W, 0402; Manufacturer: Vishay-Dale; CompType: Resistor; Value: 10.0k; Res_ohm: 10000; Value_Code: 10k0; Tolerance_%: 1; Power_W: 0.063; Value2: 0.063W; VDC_V: 50; TempCo: 100 ppm/C; SizeArea_mm2: 0.5; SizeZ_mm: 0.6; EIA_Code: E96; U/M: EA; AEC Category: Q200
R13 R16 R21 R23 R25 = CRCW040218K0FKED: RES, 18.0 k, 1%, 0.063 W, AEC-Q200 Grade 0, 0402; Manufacturer: Vishay-Dale; CompType: Resistor; Value: 18.0k; Res_ohm: 18000; Value_Code: 18k0; Tolerance_%: 1; Power_W: 0.063; Value2: 0.063W; VDC_V: 50; TempCo: 100 ppm/C; SizeArea_mm2: 0.5; SizeZ_mm: 0.6; U/M: EA; AEC Category: Q200; AEC Qualified: Y; AEC Grade: 0
R14 R19 R22 R24 R26 = CRCW040233K0JNED: RES, 33 k, 5%, 0.063 W, 0402; Manufacturer: Vishay-Dale; CompType: Resistor; Value: 33k; Res_ohm: 33000; Value_Code: 33k0; Tolerance_%: 5; Power_W: 0.063; Value2: 0.063W; VDC_V: 50; TempCo: 200 ppm/C; SizeArea_mm2: 0.5; SizeX_mm: 1; SizeZ_mm: 0.6; EIA_Code: E24; U/M: EA; AEC Category: Q200
R33 R38-R40 = CRCW0402470RJNED: as R4 on sheet TIDA-01439_CC2650
U4 = MSP432P401RIRGCR: Low-Power and High Performance 32-Bit ARM Cortex M4F With 256KB Flash and 64KB RAM, RGC0064B (VQFN-64); Alternate PartNumber: MSP432P401RIRGCT; Manufacturer: Texas Instruments; SymbolCreator: Altium; SizeArea_mm2: 81; SizeAreaWB_mm2: 121; SizeX_mm: 9; SizeZ_mm: 1; CompType: IC; U/M: EA
Y3 = FA-238 48.0000MB-W0: Crystal, 48MHz, 12pF, SMD; Manufacturer: Epson; SymbolCreator: a0412235; SizeAreaWB_mm2: 14.7; SizeArea_mm2: 8; SizeX_mm: 2.5; SizeY_mm: 3.2; SizeZ_mm: 0.7; U/M: EA; TaMin_C: -20; TaMax_C: 70; Frequency Stability: ±30ppm
Y4 = FC-12M 32.7680KA-A3: as Y2 on sheet TIDA-01439_CC2650

## Sheet TIDA-01439_RTD.SchDoc
size 431 x 279 mm; Date: Not shown in title block; ApprovedBy: Not shown in title block; CheckedBy: Not shown in title block; Author: Not shown in title block; CompanyName: Not shown in title block; Engineer: Not shown in title block; Organization: Not shown in title block; Address1: Not shown in title block; Address2: Not shown in title block; Address3: Not shown in title block; Address4: Not shown in title block; DocumentNumber: 1; Revision: Use project parameter SCH_Rev; SheetNumber: 4; SheetTotal: 7; PageSetup: Record=PageOptions¦CenterHorizontal=True¦CenterVertical=True¦PrintScale=0.62¦XCorrection=1.00¦YCorrection=1.00¦PrintKind=0¦BorderSize=5000000¦LeftOffset=0¦BottomOffset=0¦Orientation=2¦PaperLength=1000¦PaperWidth=1000¦Scale=100¦PaperSource=15¦PrintQuality=-3¦MediaType=1¦DitherType=10¦PrintScaleMode=1¦PaperKind=11x17¦PaperIndex=3
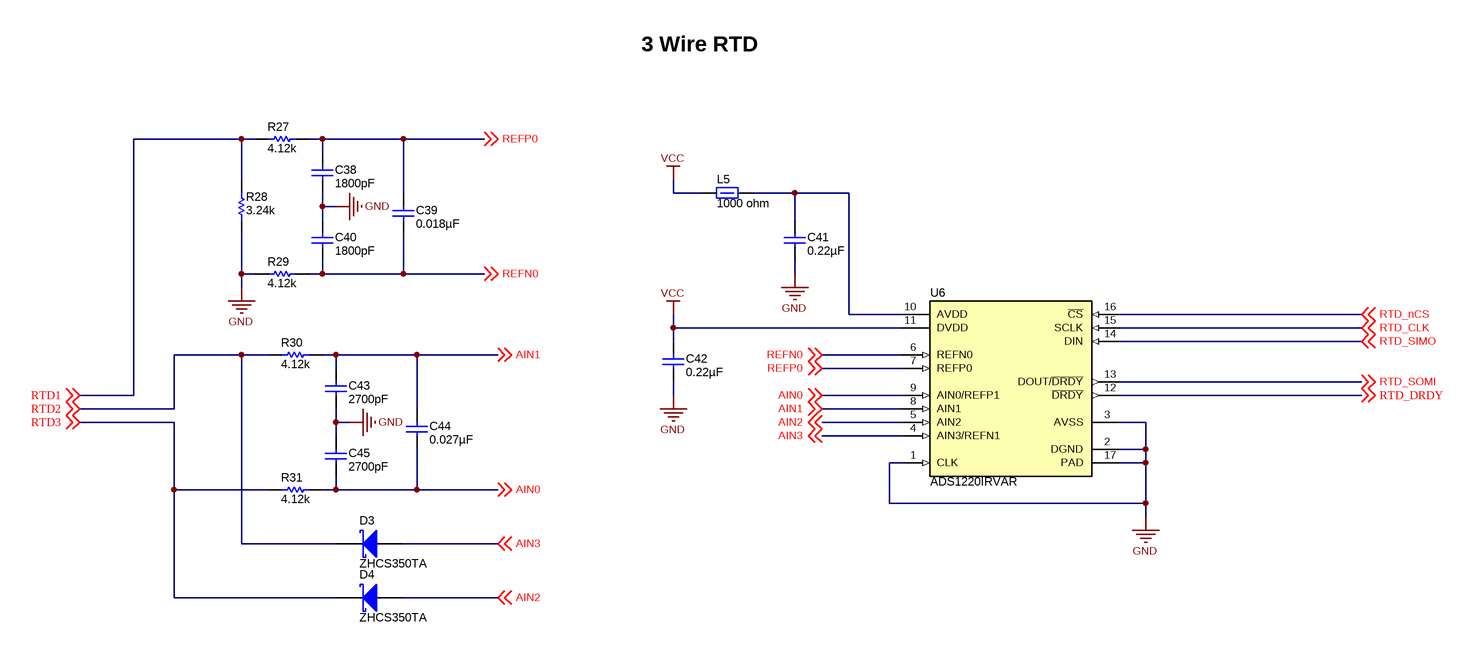
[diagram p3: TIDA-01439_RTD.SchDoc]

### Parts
C38  ValueDisplayed: 1800pF  [0402S]  (hidden comment: GRM155R72A182KA01D)
C39  ValueDisplayed: 0.018µF  [0603S]  (hidden comment: C0603C183K1RACTU)
C40  ValueDisplayed: 1800pF  [0402S]  (hidden comment: GRM155R72A182KA01D)
C41  ValueDisplayed: 0.22µF  [0402]  (hidden comment: GRM155R60J224KE01D)
C42  ValueDisplayed: 0.22µF  [0402]  (hidden comment: GRM155R60J224KE01D)
C43  ValueDisplayed: 2700pF  [0402S]  (hidden comment: GRM155R72A272KA01D)
C44  ValueDisplayed: 0.027µF  [0603S]  (hidden comment: C0603C273K1RACTU)
C45  ValueDisplayed: 2700pF  [0402S]  (hidden comment: GRM155R72A272KA01D)
D3  ZHCS350TA  [SOD-523]
D4  ZHCS350TA  [SOD-523]
L5  ValueDisplayed: 1000 ohm  [0402]  (hidden comment: BLM15HG102SN1D)
R27  value 4.12k  [0603S]  (hidden comment: RG1608P-4121-B-T5)
R28  value 3.24k  [1206L]  (hidden comment: PFC-W1206R-12-3241-B)
R29  value 4.12k  [0603S]  (hidden comment: RG1608P-4121-B-T5)
R30  value 4.12k  [0603S]  (hidden comment: RG1608P-4121-B-T5)
R31  value 4.12k  [0603S]  (hidden comment: RG1608P-4121-B-T5)
U6  ADS1220IRVAR  [RVA0016A]

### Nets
GND: C38.2 C40.1 C41.2 C42.2 C43.2 C45.1 R28.1 R29.1 U6.1(CLK) U6.2(DGND) U6.3(AVSS) U6.17(PAD)
VCC: C42.1 L5.1 U6.11(DVDD)
AIN0: C44.2 C45.2 R31.2 U6.9(AIN0/REFP1) ; off-sheet AIN0
AIN1: C43.1 C44.1 R30.2 U6.8(AIN1) ; off-sheet AIN1
AIN2: D4.2(A) U6.5(AIN2) ; off-sheet AIN2
AIN3: D3.2(A) U6.4(AIN3/REFN1) ; off-sheet AIN3
REFN0: C39.2 C40.2 R29.2 U6.6(REFN0) ; off-sheet REFN0
REFP0: C38.1 C39.1 R27.2 U6.7(REFP0) ; off-sheet REFP0
RTD1: R27.1 R28.2 ; off-sheet RTD1
RTD2: D3.1(K) R30.1 ; off-sheet RTD2
RTD3: D4.1(K) R31.1 ; off-sheet RTD3
RTD_CLK: U6.15(SCLK) ; off-sheet RTD_CLK
RTD_DRDY: U6.12(~{DRDY}) ; off-sheet RTD_DRDY
RTD_nCS: U6.16(~{CS}) ; off-sheet RTD_nCS
RTD_SIMO: U6.14(DIN) ; off-sheet RTD_SIMO
RTD_SOMI: U6.13(DOUT/~{DRDY}) ; off-sheet RTD_SOMI
NetC41_1: C41.1 L5.2 U6.10(AVDD)

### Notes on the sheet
- 3 Wire RTD

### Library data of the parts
C38 C40 = GRM155R72A182KA01D: CAP, CERM, 1800pF, 100V, +/-10%, X7R, 0402; Manufacturer: MuRata; Polarized: N; CompType: Capacitor; U/M: EA; Cap_F: 0.0000000018; Tolerance_%: 10; Value1: Unknown; VDC_V: 100; TaMin_C: -55; TaMax_C: 125; Cap_Case: 0402
C39 = C0603C183K1RACTU: CAP, CERM, 0.018uF, 100V, +/-10%, X7R, 0603; Manufacturer: Kemet; Polarized: N; CompType: Capacitor; U/M: EA; Cap_F: 0.000000018; Tolerance_%: 10; Value1: Unknown; VDC_V: 100; TaMin_C: -55; TaMax_C: 125; Cap_Case: 0603
C41 C42 = GRM155R60J224KE01D: CAP, CERM, 0.22uF, 6.3V, +/-10%, X5R, 0402; Manufacturer: MuRata; Polarized: N; CompType: Capacitor; U/M: EA; Cap_F: 0.00000022; Tolerance_%: 10; Value1: Unknown; VDC_V: 6.3; TaMin_C: -55; TaMax_C: 85
C43 C45 = GRM155R72A272KA01D: CAP, CERM, 2700pF, 100V, +/-10%, X7R, 0402; Manufacturer: MuRata; Polarized: N; CompType: Capacitor; U/M: EA; Cap_F: 0.0000000027; Tolerance_%: 10; Value1: Unknown; VDC_V: 100; TaMin_C: -55; TaMax_C: 125; Cap_Case: 0402
C44 = C0603C273K1RACTU: CAP, CERM, 0.027uF, 100V, +/-10%, X7R, 0603; Manufacturer: Kemet; Polarized: N; CompType: Capacitor; U/M: EA; Cap_F: 0.000000027; Tolerance_%: 10; Value1: Unknown; VDC_V: 100; TaMin_C: -55; TaMax_C: 125; Cap_Case: 0603
D3 D4 = ZHCS350TA: Diode, Schottky, 40V, 0.35A, SOD-523; Manufacturer: Diodes Inc.; U/M: EA; Vf_V: 0.65; Value2: 0.65V; Io_A: 0.35; Vr_V: 40
L5 = BLM15HG102SN1D: Ferrite Bead, 1000 ohm @ 100 MHz, 0.25 A, 0402; Manufacturer: MuRata; Imax_A: 0.25; DCR_ohm: 1.1; Value1: 1.1 ohm; Value2: 0.25A; SizeAreaWB_mm2: 3; SizeArea_mm2: 0.5; SizeX_mm: 1; SizeZ_mm: 0.6; ZTyp@100MHz_Ohm: 1000
R27 R29-R31 = RG1608P-4121-B-T5: RES, 4.12k ohm, 0.1%, 0.1W, 0603; Manufacturer: Susumu Co Ltd; CompType: Resistor; Res_ohm: 4120; Value_Code: 4k12; Tolerance_%: 0.1; VDC_V: 75; TempCo: 25 ppm/C; EIA_Code: E192; U/M: EA
R28 = PFC-W1206R-12-3241-B: RES, 3.24k ohm, 0.1%, 0.333W, 1206; Manufacturer: TT Electronics/IRC; CompType: Resistor; Res_ohm: 3240; Value_Code: 3k24; Tolerance_%: 0.1; Power_W: 0.333; TempCo: 10 ppm/C; EIA_Code: E192; U/M: EA
U6 = ADS1220IRVAR: 24-Bit, 2kSPS, 4-Ch, Low-Power, Delta-Sigma ADC with PGA  and Voltage Reference, RVA0016A (VQFN-16); Alternate PartNumber: ADS1220IRVAT; Manufacturer: Texas Instruments; SymbolCreator: x0208326; SizeArea_mm2: 12.25; SizeAreaWB_mm2: 20.25; SizeX_mm: 3.5; SizeZ_mm: 1; CompType: IC; U/M: EA

## Sheet TIDA-01439_Interface.SchDoc
size 431 x 279 mm; Date: Not shown in title block; ApprovedBy: Not shown in title block; CheckedBy: Not shown in title block; Author: Not shown in title block; CompanyName: Not shown in title block; Engineer: Not shown in title block; Organization: Not shown in title block; Address1: Not shown in title block; Address2: Not shown in title block; Address3: Not shown in title block; Address4: Not shown in title block; DocumentNumber: 1; Revision: Use project parameter SCH_Rev; SheetNumber: 6; SheetTotal: 7; PageSetup: Record=PageOptions¦CenterHorizontal=True¦CenterVertical=True¦PrintScale=1.00¦XCorrection=1.00¦YCorrection=1.00¦PrintKind=0¦BorderSize=5000000¦LeftOffset=0¦BottomOffset=0¦Orientation=2¦PaperLength=1000¦PaperWidth=1000¦Scale=100¦PaperSource=15¦PrintQuality=600¦MediaType=1¦DitherType=10¦PaperKind=Letter¦PrintScaleMode=1
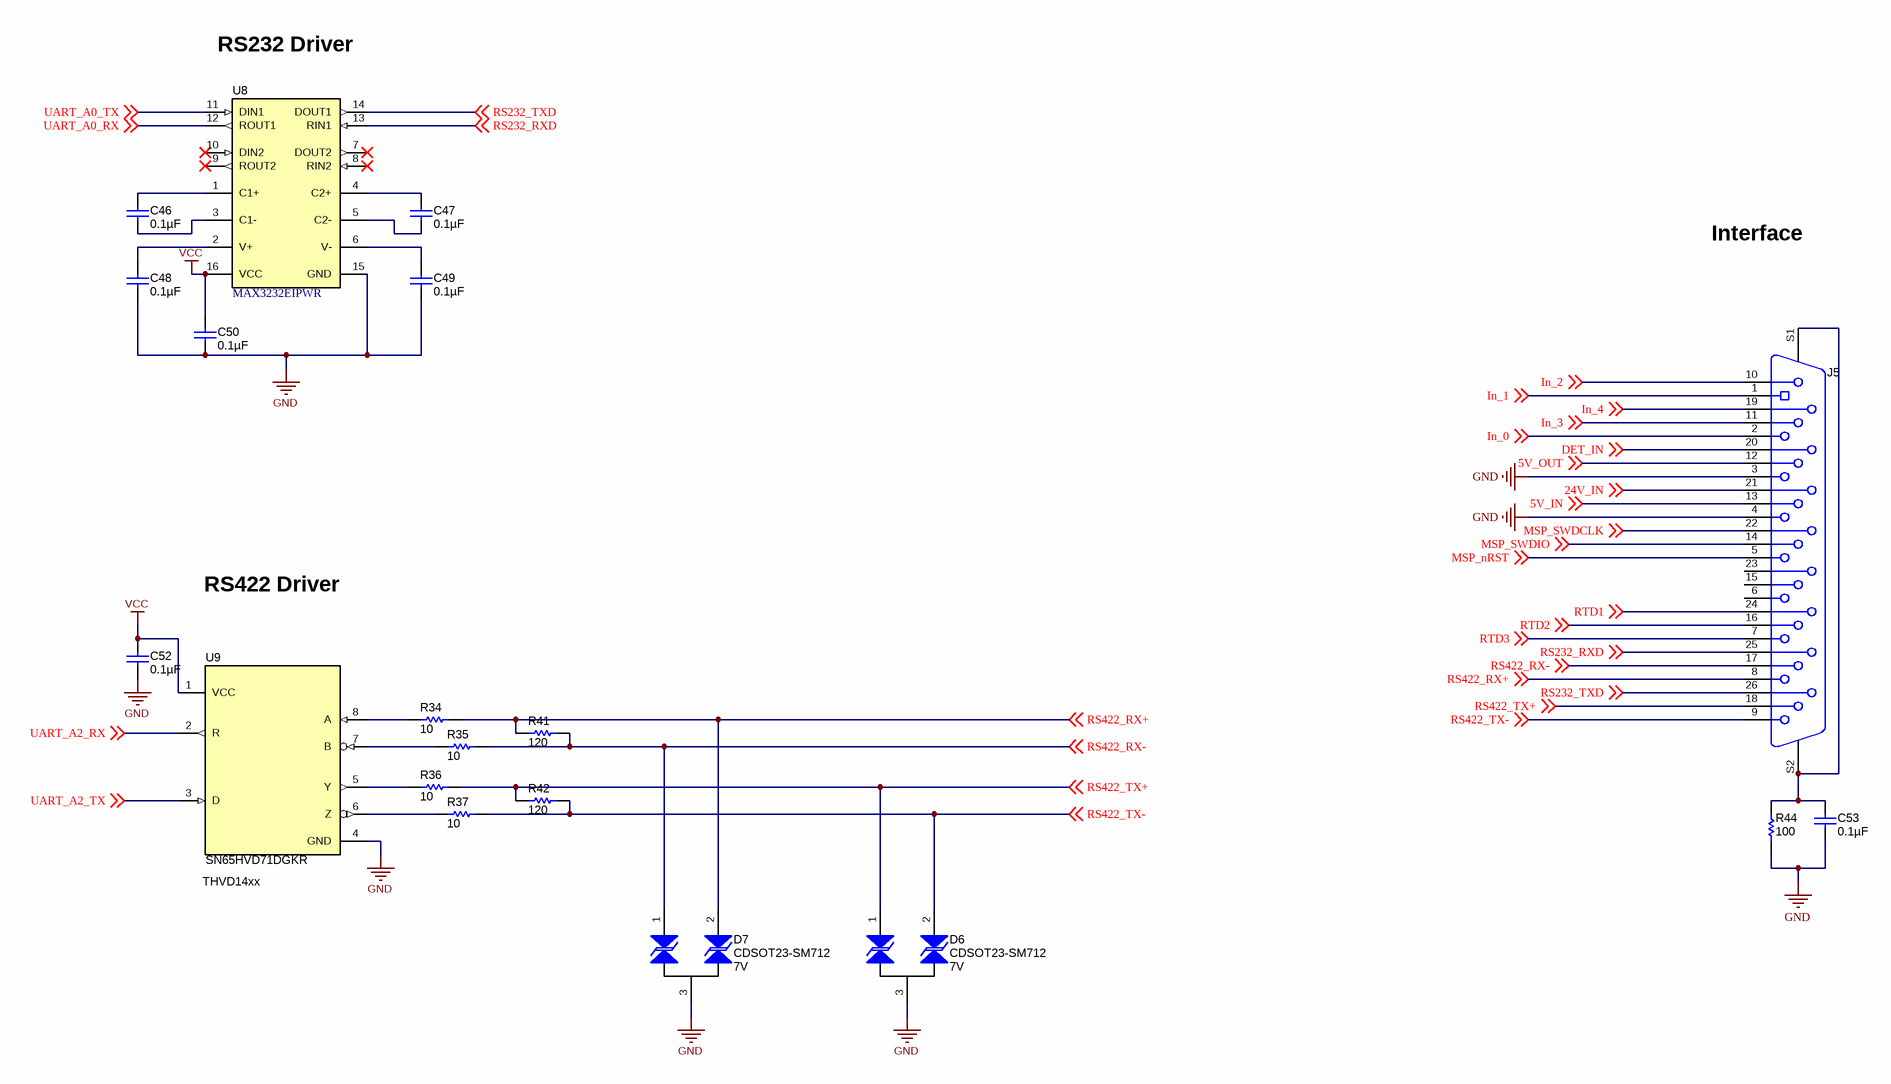
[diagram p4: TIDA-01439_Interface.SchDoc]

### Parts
C46  ValueDisplayed: 0.1µF  [0402]  (hidden comment: GRM155R70J104KA01D)
C47  ValueDisplayed: 0.1µF  [0402]  (hidden comment: GRM155R70J104KA01D)
C48  ValueDisplayed: 0.1µF  [0402]  (hidden comment: GRM155R70J104KA01D)
C49  ValueDisplayed: 0.1µF  [0402]  (hidden comment: GRM155R70J104KA01D)
C50  ValueDisplayed: 0.1µF  [0402]  (hidden comment: GRM155R70J104KA01D)
C52  ValueDisplayed: 0.1µF  [0402]  (hidden comment: GRM155R70J104KA01D)
C53  ValueDisplayed: 0.1µF  [1206_180]  (hidden comment: GRM31CR72E104KW03L)
D6  CDSOT23-SM712  value 7V  [SOT-23]
D7  CDSOT23-SM712  value 7V  [SOT-23]
J5  618026330923  [Wurth_618026330923]  (value not drawn)
R34  ValueDisplayed: 10  [0603]  (hidden comment: CRCW060310R0JNEAHP)
R35  ValueDisplayed: 10  [0603]  (hidden comment: CRCW060310R0JNEAHP)
R36  ValueDisplayed: 10  [0603]  (hidden comment: CRCW060310R0JNEAHP)
R37  ValueDisplayed: 10  [0603]  (hidden comment: CRCW060310R0JNEAHP)
R41  ValueDisplayed: 120  [0603]  (hidden comment: CRCW0603120RJNEA)
R42  ValueDisplayed: 120  [0603]  (hidden comment: CRCW0603120RJNEA)
R44  ValueDisplayed: 100  [1206]  (hidden comment: CRCW1206100RJNEA)
U8  MAX3232EIPWR  [PW0016A_N]
U9  SN65HVD71DGKR  [DGK0008A_N]

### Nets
GND: C48.2 C49.2 C50.2 C52.2 C53.1 D6.3 D7.3 J5.3 J5.4 R44.1 U8.15(GND) U9.4(GND)
VCC: C50.1 C52.1 U8.16(VCC) U9.1(VCC)
5V_IN: J5.13 ; off-sheet 5V_IN
5V_OUT: J5.12 ; off-sheet 5V_OUT
24V_IN: J5.21 ; off-sheet 24V_IN
DET_IN: J5.20 ; off-sheet DET_IN  [project net IN5_DIV]
In_0: J5.2 ; off-sheet In_0
In_1: J5.1 ; off-sheet In_1
In_2: J5.10 ; off-sheet In_2
In_3: J5.11 ; off-sheet In_3
In_4: J5.19 ; off-sheet In_4
MSP_nRST: J5.5 ; off-sheet MSP_nRST
MSP_SWDCLK: J5.22 ; off-sheet MSP_SWDCLK  [project net MSP_JTAG_TCK]
MSP_SWDIO: J5.14 ; off-sheet MSP_SWDIO  [project net MSP_JTAG_TMS]
RS232_RXD: J5.25 U8.13(RIN1) ; off-sheet RS232_RXD
RS232_TXD: J5.26 U8.14(DOUT1) ; off-sheet RS232_TXD
RS422_RX+: D7.2 J5.8 R34.2 R41.1 ; off-sheet RS422_RX+
RS422_RX-: D7.1 J5.17 R35.2 R41.2 ; off-sheet RS422_RX-
RS422_TX+: D6.1 J5.18 R36.2 R42.1 ; off-sheet RS422_TX+
RS422_TX-: D6.2 J5.9 R37.2 R42.2 ; off-sheet RS422_TX-
RTD1: J5.24 ; off-sheet RTD1
RTD2: J5.16 ; off-sheet RTD2
RTD3: J5.7 ; off-sheet RTD3
UART_A0_RX: U8.12(ROUT1) ; off-sheet UART_A0_RX
UART_A0_TX: U8.11(DIN1) ; off-sheet UART_A0_TX
UART_A2_RX: U9.2(R) ; off-sheet UART_A2_RX
UART_A2_TX: U9.3(D) ; off-sheet UART_A2_TX
NetC46_1: C46.1 U8.1(C1+)
NetC46_2: C46.2 U8.3(C1-)
NetC47_1: C47.1 U8.4(C2+)
NetC47_2: C47.2 U8.5(C2-)
NetC48_1: C48.1 U8.2(V+)
NetC49_1: C49.1 U8.6(V-)
NetC53_2: C53.2 J5.S1 J5.S2 R44.2
NetR34_1: R34.1 U9.8(A)
NetR35_1: R35.1 U9.7(B)
NetR36_1: R36.1 U9.5(Y)
NetR37_1: R37.1 U9.6(Z)

Not connected (* = marked no-connect by the designer): J5 6 15 23; U8 7(DOUT2)* 8(RIN2)* 9(ROUT2)* 10(DIN2)*

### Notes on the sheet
- RS232 Driver
- Interface
- RS422 Driver
- (near U9) THVD14xx

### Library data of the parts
C46-C50 C52 = GRM155R70J104KA01D: as C6 on sheet TIDA-01439_MSP432
C53 = GRM31CR72E104KW03L: CAP, CERM, 0.1 µF, 250 V, +/- 10%, X7R, 1206; Manufacturer: MuRata; Polarized: N; CompType: Capacitor; Value: 0.1uF; U/M: EA; Cap_F: 0.0000001; Tolerance_%: 10; Value1: Unknown; VDC_V: 250; Value2: 250V; TaMin_C: -55; TaMax_C: 125; Cap_Case: 1206; SizeArea_mm2: 5.12; SizeAreaWB_mm2: 10.92; SizeX_mm: 3.2; SizeY_mm: 1.6; SizeZ_mm: 1.8; AEC Category: Q200
D6 D7 = CDSOT23-SM712: Diode, TVS, Bi, 7 V, SOT-23; Manufacturer: Bourns; SymbolCreator: a0411947; U/M: EA; Vr_V: 7; Value1: W; SizeAreaWB_mm2: 14; SizeArea_mm2: 7.5; SizeX_mm: 2.5; SizeY_mm: 3; SizeZ_mm: 1.1; AEC Category: Q101
J5 = 618026330923: Receptacle, D-Sub, 2.29mm, 27 Pos, Gold, R/A, TH; Manufacturer: Wurth Elektronik; SymbolCreator: Altium; Pitch_mm: 2.29; Gender: Female; Row_Count: 3; RowSpacing_mm: 2.54; Voltage_V: 60; Cert_UL: Y
R34-R37 = CRCW060310R0JNEAHP: RES, 10, 5%, 0.25 W, 0603; Manufacturer: Vishay-Dale; CompType: Resistor; Value: 10; Value_Code: 10R0; Tolerance_%: 5; Power_W: 0.25; Value2: 0.25W; VDC_V: 75; TempCo: 200 ppm/C; SizeArea_mm2: 1.28; SizeX_mm: 1.6; SizeY_mm: 0.8; SizeZ_mm: 1; EIA_Code: E24; U/M: EA; AEC Category: Q200
R41 R42 = CRCW0603120RJNEA: RES, 120, 5%, 0.1 W, 0603; Manufacturer: Vishay-Dale; CompType: Resistor; Value: 120; Value_Code: 120R; Tolerance_%: 5; Power_W: 0.1; Value2: 0.1W; VDC_V: 75; TempCo: 200 ppm/C; SizeArea_mm2: 1.28; SizeX_mm: 1.6; SizeY_mm: 0.8; SizeZ_mm: 1; EIA_Code: E24; U/M: EA; AEC Category: Q200
R44 = CRCW1206100RJNEA: RES, 100, 5%, 0.25 W, 1206; Manufacturer: Vishay-Dale; CompType: Resistor; Value: 100; Value_Code: 100R; Tolerance_%: 5; Power_W: 0.25; Value2: 0.25W; VDC_V: 200; TempCo: 200 ppm/C; SizeArea_mm2: 5.12; SizeX_mm: 3.2; SizeY_mm: 1.6; SizeZ_mm: 1.35; EIA_Code: E24; U/M: EA; AEC Category: Q200
U8 = MAX3232EIPWR: 3-V to 5.5-V Multichannel RS-232 Line Driver / Receiver with ±15-kV IEC ESD Protection, -40 to 85 degC, 16-Pin TSSOP (PW), Green (RoHS & no Sb/Br); Manufacturer: Texas Instruments; Alternate PartNumber: Equivalent; Drivers Per Package: 2; Supply Voltage(s)(V): 3.3 or 5.0; ESD HBM(kV): +/-15; ICC(Max)(mA): 1; Single Supply: TRUE
U9 = SN65HVD71DGKR: 3.3-V Full-Duplex RS-485 Transceivers With 12-kV IEC ESD, DGK0008A (VSSOP-8); Manufacturer: Texas Instruments; SymbolCreator: a0799628; SizeArea_mm2: 15.655; SizeAreaWB_mm2: 35.955; SizeX_mm: 5.05; SizeY_mm: 3.1; SizeZ_mm: 1.1; CompType: IC; U/M: EA

## Sheet TIDA-01439_Powersupply.SchDoc
size 431 x 279 mm; Date: Not shown in title block; ApprovedBy: Not shown in title block; CheckedBy: Not shown in title block; Author: Not shown in title block; CompanyName: Not shown in title block; Engineer: Not shown in title block; Organization: Not shown in title block; Address1: Not shown in title block; Address2: Not shown in title block; Address3: Not shown in title block; Address4: Not shown in title block; DocumentNumber: 1; Revision: Use project parameter SCH_Rev; SheetNumber: 5; SheetTotal: 7; PageSetup: Record=PageOptions¦CenterHorizontal=True¦CenterVertical=True¦PrintScale=1.00¦XCorrection=1.00¦YCorrection=1.00¦PrintKind=0¦BorderSize=5000000¦LeftOffset=0¦BottomOffset=0¦Orientation=2¦PaperLength=1000¦PaperWidth=1000¦Scale=100¦PaperSource=15¦PrintQuality=600¦MediaType=1¦DitherType=10¦PaperKind=Letter¦PrintScaleMode=1
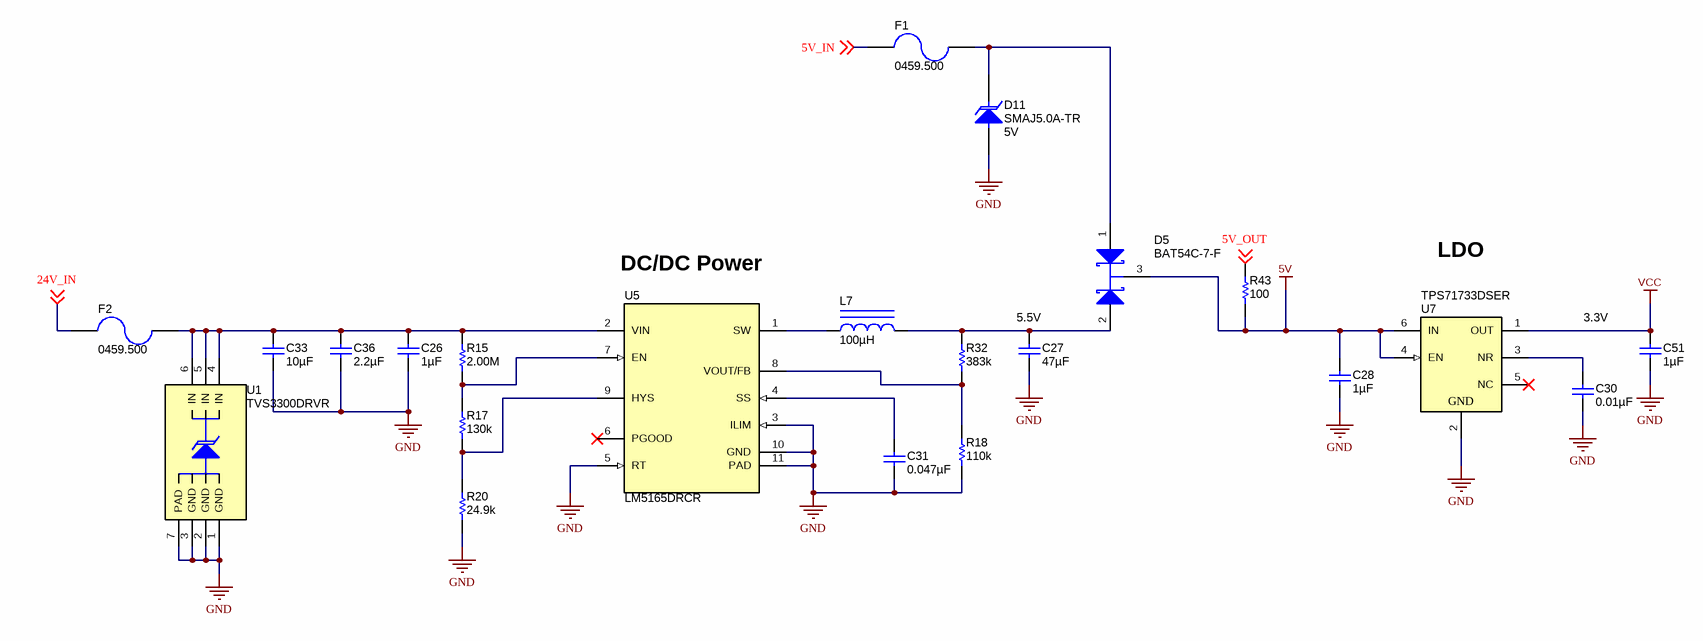
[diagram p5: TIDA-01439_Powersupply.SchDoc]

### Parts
C26  ValueDisplayed: 1µF  [1206_180]  (hidden comment: GRM31CR72A105KA01L)
C27  ValueDisplayed: 47µF  [1210_270]  (hidden comment: GRM32ER71A476KE15L)
C28  ValueDisplayed: 1µF  [0402]  (hidden comment: C1005X7S1A105K050BC)
C30  ValueDisplayed: 0.01µF  [0402]  (hidden comment: C1005X7R1C103K050BA)
C31  ValueDisplayed: 0.047µF  [0402]  (hidden comment: GRM155R71C473KA01D)
C33  ValueDisplayed: 10µF  [1210_270]  (hidden comment: GRM32ER71J106KA12L)
C36  ValueDisplayed: 2.2µF  [1206]  (hidden comment: UMK316B7225KL-T)
C51  ValueDisplayed: 1µF  [0402]  (hidden comment: C1005X7S1A105K050BC)
D5  BAT54C-7-F  [SOT-23]
D11  SMAJ5.0A-TR  value 5V  [SMA]
F1  0459.500  [PicoSMF459]
F2  0459.500  [PicoSMF459]
L7  ValueDisplayed: 100µH  [WE-TPC-LH]  (hidden comment: 744053101)
R15  ValueDisplayed: 2.00M  [0402]  (hidden comment: CRCW04022M00FKED)
R17  ValueDisplayed: 130k  [0402]  (hidden comment: CRCW0402130KJNED)
R18  ValueDisplayed: 110k  [0402]  (hidden comment: CRCW0402110KFKED)
R20  ValueDisplayed: 24.9k  [0402]  (hidden comment: CRCW040224K9FKED)
R32  ValueDisplayed: 383k  [0402]  (hidden comment: CRCW0402383KFKED)
R43  ValueDisplayed: 100  [1206]  (hidden comment: CRCW1206100RJNEA)
U1  TVS3300DRVR  [DRV0006A]
U5  LM5165DRCR  [DRC0010J]
U7  TPS71733DSER  [DSE0006A]

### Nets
5V: C28.1 D5.3(K) R43.1 U7.4(EN) U7.6(IN)
GND: C26.2 C27.2 C28.2 C30.2 C31.2 C33.2 C36.2 C51.2 D11.2(A) R18.1 R20.1 U1.1(GND) U1.2(GND) U1.3(GND) U1.7(PAD) U5.3(ILIM) U5.5(RT) U5.10(GND) U5.11(PAD) U7.2(GND)
VCC: C51.1 U7.1(OUT)
5V_IN: F1.2 ; off-sheet 5V_IN
5V_OUT: R43.2 ; off-sheet 5V_OUT
24V_IN: F2.2 ; off-sheet 24V_IN
NetC26_1: C26.1 C33.1 C36.1 F2.1 R15.2 U1.4(IN) U1.5(IN) U1.6(IN) U5.2(VIN)
NetC27_1: C27.1 D5.2(A2) L7.2 R32.2
NetC30_1: C30.1 U7.3(NR)
NetC31_1: C31.1 U5.4(SS)
NetD5_1: D5.1(A1) D11.1(K) F1.1
NetL7_1: L7.1 U5.1(SW)
NetR15_1: R15.1 R17.2 U5.7(EN)
NetR17_1: R17.1 R20.2 U5.9(HYS)
NetR18_2: R18.2 R32.1 U5.8(VOUT/FB)

Not connected (* = marked no-connect by the designer): U5 6(PGOOD)*; U7 5(NC)*

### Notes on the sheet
- DC/DC Power
- LDO
- (near C27) 5.5V
- 3.3V

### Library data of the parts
C26 = GRM31CR72A105KA01L: CAP, CERM, 1 µF, 100 V, +/- 10%, X7R, 1206; Manufacturer: MuRata; Polarized: N; CompType: Capacitor; Value: 1uF; U/M: EA; Cap_F: 0.000001; Tolerance_%: 10; Value1: Unknown; VDC_V: 100; Value2: 100V; TaMin_C: -55; TaMax_C: 125; Cap_Case: 2220; SizeArea_mm2: 5.12; SizeAreaWB_mm2: 10.92; SizeX_mm: 3.2; SizeY_mm: 1.6; SizeZ_mm: 1.8; AEC Category: Q200
C27 = GRM32ER71A476KE15L: CAP, CERM, 47 µF, 10 V, +/- 10%, X7R, 1210; Manufacturer: MuRata; Polarized: N; CompType: Capacitor; Value: 47uF; U/M: EA; Cap_F: 0.000047; Tolerance_%: 10; Value1: Unknown; Value2: 10V; TaMin_C: -55; TaMax_C: 125; Cap_Case: 1210; SizeArea_mm2: 8; SizeAreaWB_mm2: 14.7; SizeX_mm: 3.2; SizeY_mm: 2.5; SizeZ_mm: 2.7; AEC Category: Q200
C28 C51 = C1005X7S1A105K050BC: CAP, CERM, 1 µF, 10 V, +/- 10%, X7S, 0402; Manufacturer: TDK; Polarized: N; CompType: Capacitor; Value: 1uF; U/M: EA; Cap_F: 0.000001; Tolerance_%: 10; Value1: Unknown; Value2: 10V; TaMin_C: -55; TaMax_C: 125; AEC Category: Q200
C30 = C1005X7R1C103K050BA: CAP, CERM, 0.01 µF, 16 V, +/- 10%, X7R, 0402; Manufacturer: TDK; Polarized: N; CompType: Capacitor; Value: 0.01uF; U/M: EA; Cap_F: 0.00000001; Tolerance_%: 10; ESR_ohm: 0.0623; Value1: 0.0623 ohm; VDC_V: 16; Value2: 16V; TaMin_C: -55; TaMax_C: 125; AEC Category: Q200
C31 = GRM155R71C473KA01D: CAP, CERM, 0.047 µF, 16 V, +/- 10%, X7R, 0402; Manufacturer: MuRata; Polarized: N; CompType: Capacitor; Value: 0.047uF; U/M: EA; Cap_F: 0.000000047; Tolerance_%: 10; Value1: Unknown; VDC_V: 16; Value2: 16V; TaMin_C: -55; TaMax_C: 125; AEC Category: Q200
C33 = GRM32ER71J106KA12L: CAP, CERM, 10 µF, 63 V, +/- 10%, X7R, 1210; Manufacturer: MuRata; Polarized: N; CompType: Capacitor; Value: 10uF; U/M: EA; Cap_F: 0.00001; Tolerance_%: 10; Value1: Unknown; VDC_V: 63; Value2: 63V; TaMin_C: -55; TaMax_C: 125; Cap_Case: 1210; SizeArea_mm2: 8; SizeAreaWB_mm2: 14.7; SizeX_mm: 3.2; SizeY_mm: 2.5; SizeZ_mm: 2.7; AEC Category: Q200
C36 = UMK316B7225KL-T: CAP, CERM, 2.2 µF, 50 V, +/- 10%, X7R, 1206; Manufacturer: Taiyo Yuden; Polarized: N; CompType: Capacitor; Value: 2.2uF; U/M: EA; Cap_F: 0.0000022; Tolerance_%: 10; Value1: Unknown; VDC_V: 50; Value2: 50V; TaMin_C: -55; TaMax_C: 125; SizeArea_mm2: 5.12; SizeAreaWB_mm2: 10.92; SizeX_mm: 3.2; SizeY_mm: 1.6; SizeZ_mm: 1.35; AEC Category: Q200
D5 = BAT54C-7-F: Diode, Schottky, 30 V, 0.2 A, SOT-23; Manufacturer: Diodes Inc.; U/M: EA; Vf_V: 0.65; Value: 30V; Value1: 0.2A; Value2: 0.65V; Io_A: 0.2; Vr_V: 30; TJmax_C: 125; SizeAreaWB_mm2: 14; SizeArea_mm2: 7.5; SizeX_mm: 2.5; SizeY_mm: 3; SizeZ_mm: 1.1; AEC Category: Q101
D11 = SMAJ5.0A-TR: Diode, TVS, Uni, 5 V, 13.4 Vc, SMA; Manufacturer: STMicroelectronics; U/M: EA; Vr_V: 5; Value1: W; RJA_CperW: 120; SizeAreaWB_mm2: 37.3428; SizeArea_mm2: 16.3228; SizeX_mm: 5.59; SizeY_mm: 2.92; SizeZ_mm: 2.87; AEC Category: Q101; AEC Qualified: N
F1 F2 = 0459.500: Fuse, 0.5 A, 125VAC/VDC, SMD; Manufacturer: Littelfuse; VDC_V: 125; Interrupt_DC: 300; Interrupt_AC: 50; Irating_A: 0.5; Rtyp_Ohm: 0.28; MeltingTyp: 0.0546
L7 = 744053101: Inductor, Shielded Drum Core, Ferrite, 100 µH, 0.45 A, 0.36 ohm, SMD; Manufacturer: Wurth Elektronik; Value: 100uH; Ind_H: 100.0E-6; Imax_A: 0.45; Irms: 0.45A @ 30C rise; Isat: 0.45A @ 35% inductance drop; DCR_ohm: 0.36; Value2: 0.45A; SizeAreaWB_mm2: 60.84; SizeArea_mm2: 33.64; SizeX_mm: 5.8; SizeZ_mm: 2.8; AEC Category: Q200
R15 = CRCW04022M00FKED: RES, 2.00 M, 1%, 0.063 W, 0402; Manufacturer: Vishay-Dale; CompType: Resistor; Value: 2.00Meg; Res_ohm: 2000000; Value_Code: 2M00; Tolerance_%: 1; Power_W: 0.063; Value2: 0.063W; VDC_V: 50; TempCo: 100 ppm/C; EIA_Code: E96; U/M: EA; AEC Category: Q200
R17 = CRCW0402130KJNED: RES, 130 k, 5%, 0.063 W, 0402; Manufacturer: Vishay-Dale; CompType: Resistor; Value: 130k; Res_ohm: 130000; Tolerance_%: 5; Power_W: 0.063; Value2: 0.063W; VDC_V: 50; TempCo: 200 ppm/C; SizeArea_mm2: 0.5; SizeX_mm: 1; SizeZ_mm: 0.6; EIA_Code: E24; U/M: EA; AEC Category: Q200
R18 = CRCW0402110KFKED: RES, 110 k, 1%, 0.063 W, 0402; Manufacturer: Vishay-Dale; CompType: Resistor; Value: 110k; Res_ohm: 110000; Tolerance_%: 1; Power_W: 0.063; Value2: 0.063W; VDC_V: 50; TempCo: 100 ppm/C; SizeArea_mm2: 0.5; SizeZ_mm: 0.6; EIA_Code: E96; U/M: EA; AEC Category: Q200
R20 = CRCW040224K9FKED: RES, 24.9 k, 1%, 0.063 W, 0402; Manufacturer: Vishay-Dale; CompType: Resistor; Value: 24.9k; Res_ohm: 24900; Value_Code: 24k9; Tolerance_%: 1; Power_W: 0.063; Value2: 0.063W; VDC_V: 50; TempCo: 100 ppm/C; SizeArea_mm2: 0.5; SizeZ_mm: 0.6; EIA_Code: E96; U/M: EA; AEC Category: Q200
R32 = CRCW0402383KFKED: RES, 383 k, 1%, 0.063 W, 0402; Manufacturer: Vishay-Dale; CompType: Resistor; Value: 383k; Res_ohm: 383000; Tolerance_%: 1; Power_W: 0.063; Value2: 0.063W; VDC_V: 50; TempCo: 100 ppm/C; SizeArea_mm2: 0.5; SizeZ_mm: 0.6; EIA_Code: E96; U/M: EA; AEC Category: Q200
R43 = CRCW1206100RJNEA: as R44 on sheet TIDA-01439_Interface
U1 = TVS3300DRVR: 33V Precision Surge Protection Clamp, DRV0006A (WSON-6); Alternate PartNumber: TVS3300DRVT; Manufacturer: Texas Instruments; SymbolCreator: Altium; SizeArea_mm2: 4; SizeAreaWB_mm2: 9; SizeX_mm: 2; SizeZ_mm: 0.8; CompType: IC; U/M: EA
U5 = LM5165DRCR: 3V-65V, 150mA Synchronous Buck Converter With Ultra-Low IQ, DRC0010J (VSON-10); Alternate PartNumber: LM5165DRCT; Manufacturer: Texas Instruments; SymbolCreator: Altium; SizeArea_mm2: 9; SizeAreaWB_mm2: 16; SizeX_mm: 3; SizeZ_mm: 1; CompType: IC; U/M: EA
U7 = TPS71733DSER: Single Output High PSRR LDO, 150 mA, Fixed 3.3 V Output, 2.5 to 6.5 V Input, with Low IQ, 6-pin WSON (DSE), -40 to 125 degC, Green (RoHS & no Sb/Br); Manufacturer: Texas Instruments; Alternate PartNumber: Equivalent; Accuracy(%): 3; Fixed Output Options(V): 3.3; Iout(Max)(A): 0.15; Iq(Typ)(mA): 0.05; SubFamily: Single Channel LDO; Vdo(Typ)(mV): 170; Vin(Max)(V): 6.5; Vin(Min)(V): 2.5

## Sheet TIDA-01439_EVM_Hardware.SchDoc
size 431 x 279 mm; Date: Not shown in title block; ApprovedBy: Not shown in title block; CheckedBy: Not shown in title block; Author: Not shown in title block; CompanyName: Not shown in title block; Engineer: Not shown in title block; Organization: Not shown in title block; Address1: Not shown in title block; Address2: Not shown in title block; Address3: Not shown in title block; Address4: Not shown in title block; DocumentNumber: 1; Revision: Use project parameter SCH_Rev; SheetNumber: 7; SheetTotal: 7; PageSetup: Record=PageOptions¦CenterHorizontal=True¦CenterVertical=True¦PrintScale=1.00¦XCorrection=1.00¦YCorrection=1.00¦PrintKind=0¦BorderSize=5000000¦LeftOffset=0¦BottomOffset=0¦Orientation=2¦PaperLength=1000¦PaperWidth=1000¦Scale=100¦PaperSource=15¦PrintQuality=600¦MediaType=1¦DitherType=10¦PaperKind=Letter¦PrintScaleMode=1
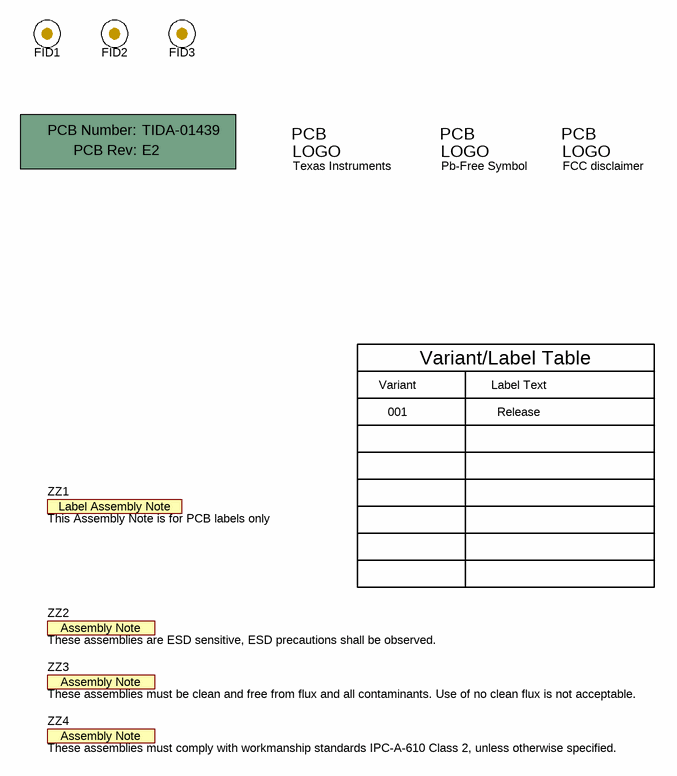
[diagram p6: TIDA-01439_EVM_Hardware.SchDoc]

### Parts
!PCB1  Printed Circuit Board  (value not drawn)  (mechanical)
FID1  Fiducial  [Fiducial10-20]  (value not drawn)
FID2  Fiducial  [Fiducial10-20]  (value not drawn)
FID3  Fiducial  [Fiducial10-20]  (value not drawn)
Logo1  Texas Instruments  [TI_Stacked_Overlay_Small]  (no BOM)
Logo2  Pb-Free Symbol  [Pb-Free_Overlay_Small]  (no BOM)
Logo3  FCC disclaimer  [FCC_disclaimer]  (no BOM)
ZZ1  This Assembly Note is for PCB labels only  [AssemblyNoteLabel]  (no BOM)
ZZ2  These assemblies are ESD sensitive, ESD precautions shall be observed.  [AssemblyNote]  (no BOM)
ZZ3  These assemblies must be clean and free from flux and all contaminants. Use of no clean flux is not acceptable.  [AssemblyNote]  (no BOM)
ZZ4  These assemblies must comply with workmanship standards IPC-A-610 Class 2, unless otherwise specified.  [AssemblyNote]  (no BOM)

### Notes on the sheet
- Variant
- Variant/Label Table
- Label Text
- 001
- Release

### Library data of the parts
!PCB1 = PCB: Manufacturer: Any; PartNumber: TIDA-01439; SymbolCreator: a0412235
FID1-FID3 = Fiducial: Fiducial mark.  There is nothing to buy or mount.; SymbolCreator: codlsc
Logo1 = TI_Logo: Texas Instrument Corporate Signature; SymbolCreator: codlsc
Logo2 = Pb-Free: SymbolCreator: a0412235
Logo3 = FCC_disclaimer: SymbolCreator: codlsc
ZZ1 = AssemblyNoteLabel: SymbolCreator: a0412235
ZZ2-ZZ4 = AssemblyNote: SymbolCreator: codlsc

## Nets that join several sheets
5V: TIDA-01439_MSP432 (C6.1 J4.6 J4.7), TIDA-01439_Powersupply (5 pins)
GND: TIDA-01439_CC2650 (31 pins), TIDA-01439_MSP432 (40 pins), TIDA-01439_RTD (12 pins), TIDA-01439_Interface (12 pins), TIDA-01439_Powersupply (20 pins)
VCC: TIDA-01439_CC2650 (J3.1 L1.2), TIDA-01439_MSP432 (6 pins), TIDA-01439_RTD (C42.1 L5.1 U6.11), TIDA-01439_Interface (C50.1 C52.1 U8.16 U9.1), TIDA-01439_Powersupply (C51.1 U7.1)
5V_IN: TIDA-01439_Interface (J5.13), TIDA-01439_Powersupply (F1.2)
5V_OUT: TIDA-01439_Interface (J5.12), TIDA-01439_Powersupply (R43.2)
24V_IN: TIDA-01439_Interface (J5.21), TIDA-01439_Powersupply (F2.2)
CC2650_CLK: TIDA-01439_CC2650 (U3.26), TIDA-01439_MSP432 (U4.14)
CC2650_nCS: TIDA-01439_CC2650 (U3.24), TIDA-01439_MSP432 (U4.13)
CC2650_SIMO: TIDA-01439_CC2650 (U3.25), TIDA-01439_MSP432 (U4.16)
CC2650_SOMI: TIDA-01439_CC2650 (U3.23), TIDA-01439_MSP432 (U4.15)
IN5_DIV: TIDA-01439_MSP432 (R11.1 U4.44), TIDA-01439_Interface (J5.20)
In_0: TIDA-01439_MSP432 (R25.2), TIDA-01439_Interface (J5.2)
In_1: TIDA-01439_MSP432 (R23.2), TIDA-01439_Interface (J5.1)
In_2: TIDA-01439_MSP432 (R21.2), TIDA-01439_Interface (J5.10)
In_3: TIDA-01439_MSP432 (R16.2), TIDA-01439_Interface (J5.11)
In_4: TIDA-01439_MSP432 (R13.2), TIDA-01439_Interface (J5.19)
MSP_JTAG_TCK: TIDA-01439_MSP432 (J6.4 U4.64), TIDA-01439_Interface (J5.22)
MSP_JTAG_TMS: TIDA-01439_MSP432 (J6.2 U4.63), TIDA-01439_Interface (J5.14)
MSP_nRST: TIDA-01439_MSP432 (C34.1 J6.10 R9.1 U4.52), TIDA-01439_Interface (J5.5)
P3.0: TIDA-01439_CC2650 (R2.2), TIDA-01439_MSP432 (J11.2 U4.19)
RTD1: TIDA-01439_RTD (R27.1 R28.2), TIDA-01439_Interface (J5.24)
RTD2: TIDA-01439_RTD (D3.1 R30.1), TIDA-01439_Interface (J5.16)
RTD3: TIDA-01439_RTD (D4.1 R31.1), TIDA-01439_Interface (J5.7)
RTD_CLK: TIDA-01439_MSP432 (U4.6), TIDA-01439_RTD (U6.15)
RTD_DRDY: TIDA-01439_MSP432 (U4.45), TIDA-01439_RTD (U6.12)
RTD_nCS: TIDA-01439_MSP432 (U4.5), TIDA-01439_RTD (U6.16)
RTD_SIMO: TIDA-01439_MSP432 (U4.7), TIDA-01439_RTD (U6.14)
RTD_SOMI: TIDA-01439_MSP432 (U4.8), TIDA-01439_RTD (U6.13)
UART_A0_RX: TIDA-01439_MSP432 (U4.3), TIDA-01439_Interface (U8.12)
UART_A0_TX: TIDA-01439_MSP432 (U4.4), TIDA-01439_Interface (U8.11)
UART_A2_RX: TIDA-01439_MSP432 (U4.21), TIDA-01439_Interface (U9.2)
UART_A2_TX: TIDA-01439_MSP432 (U4.22), TIDA-01439_Interface (U9.3)

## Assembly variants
001: not fitted C1 C10 C11 FID1 FID2 FID3 J1 J11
